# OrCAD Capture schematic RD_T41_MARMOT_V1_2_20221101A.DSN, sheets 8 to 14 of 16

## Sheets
8 PAGE08_AUDIO: size A3
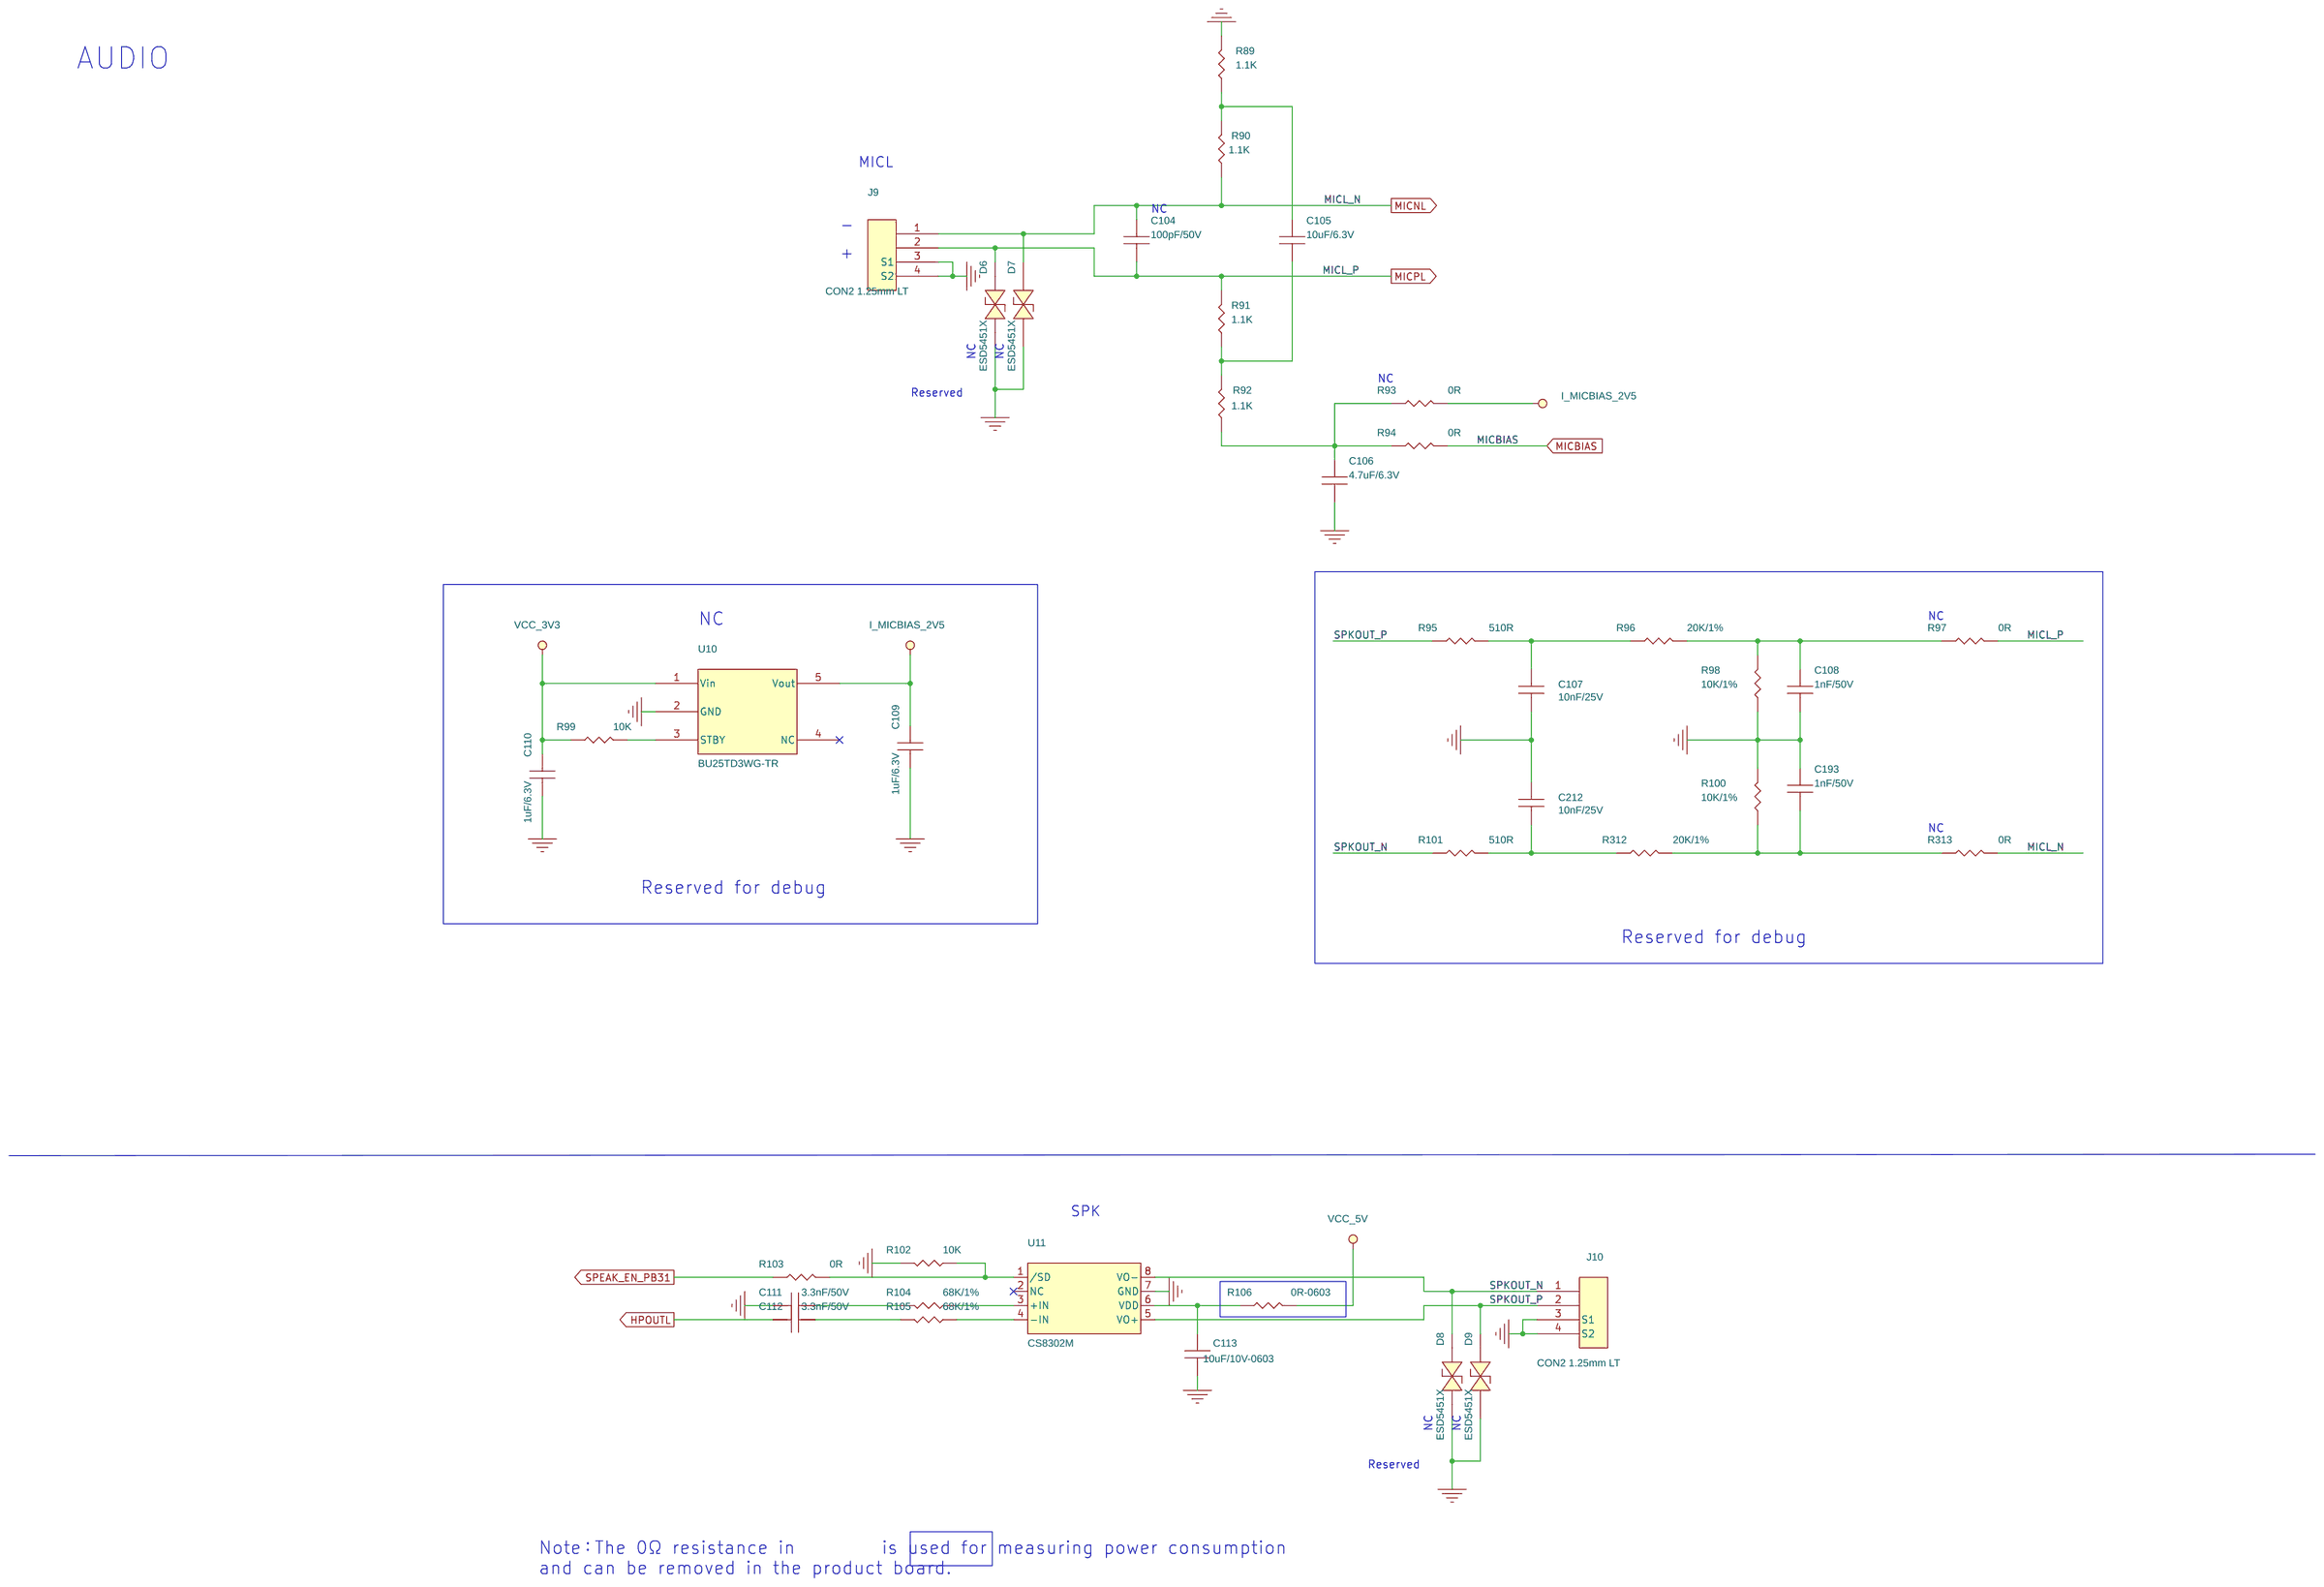
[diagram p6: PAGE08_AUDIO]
9 PAGE09_CAMERA: size A3
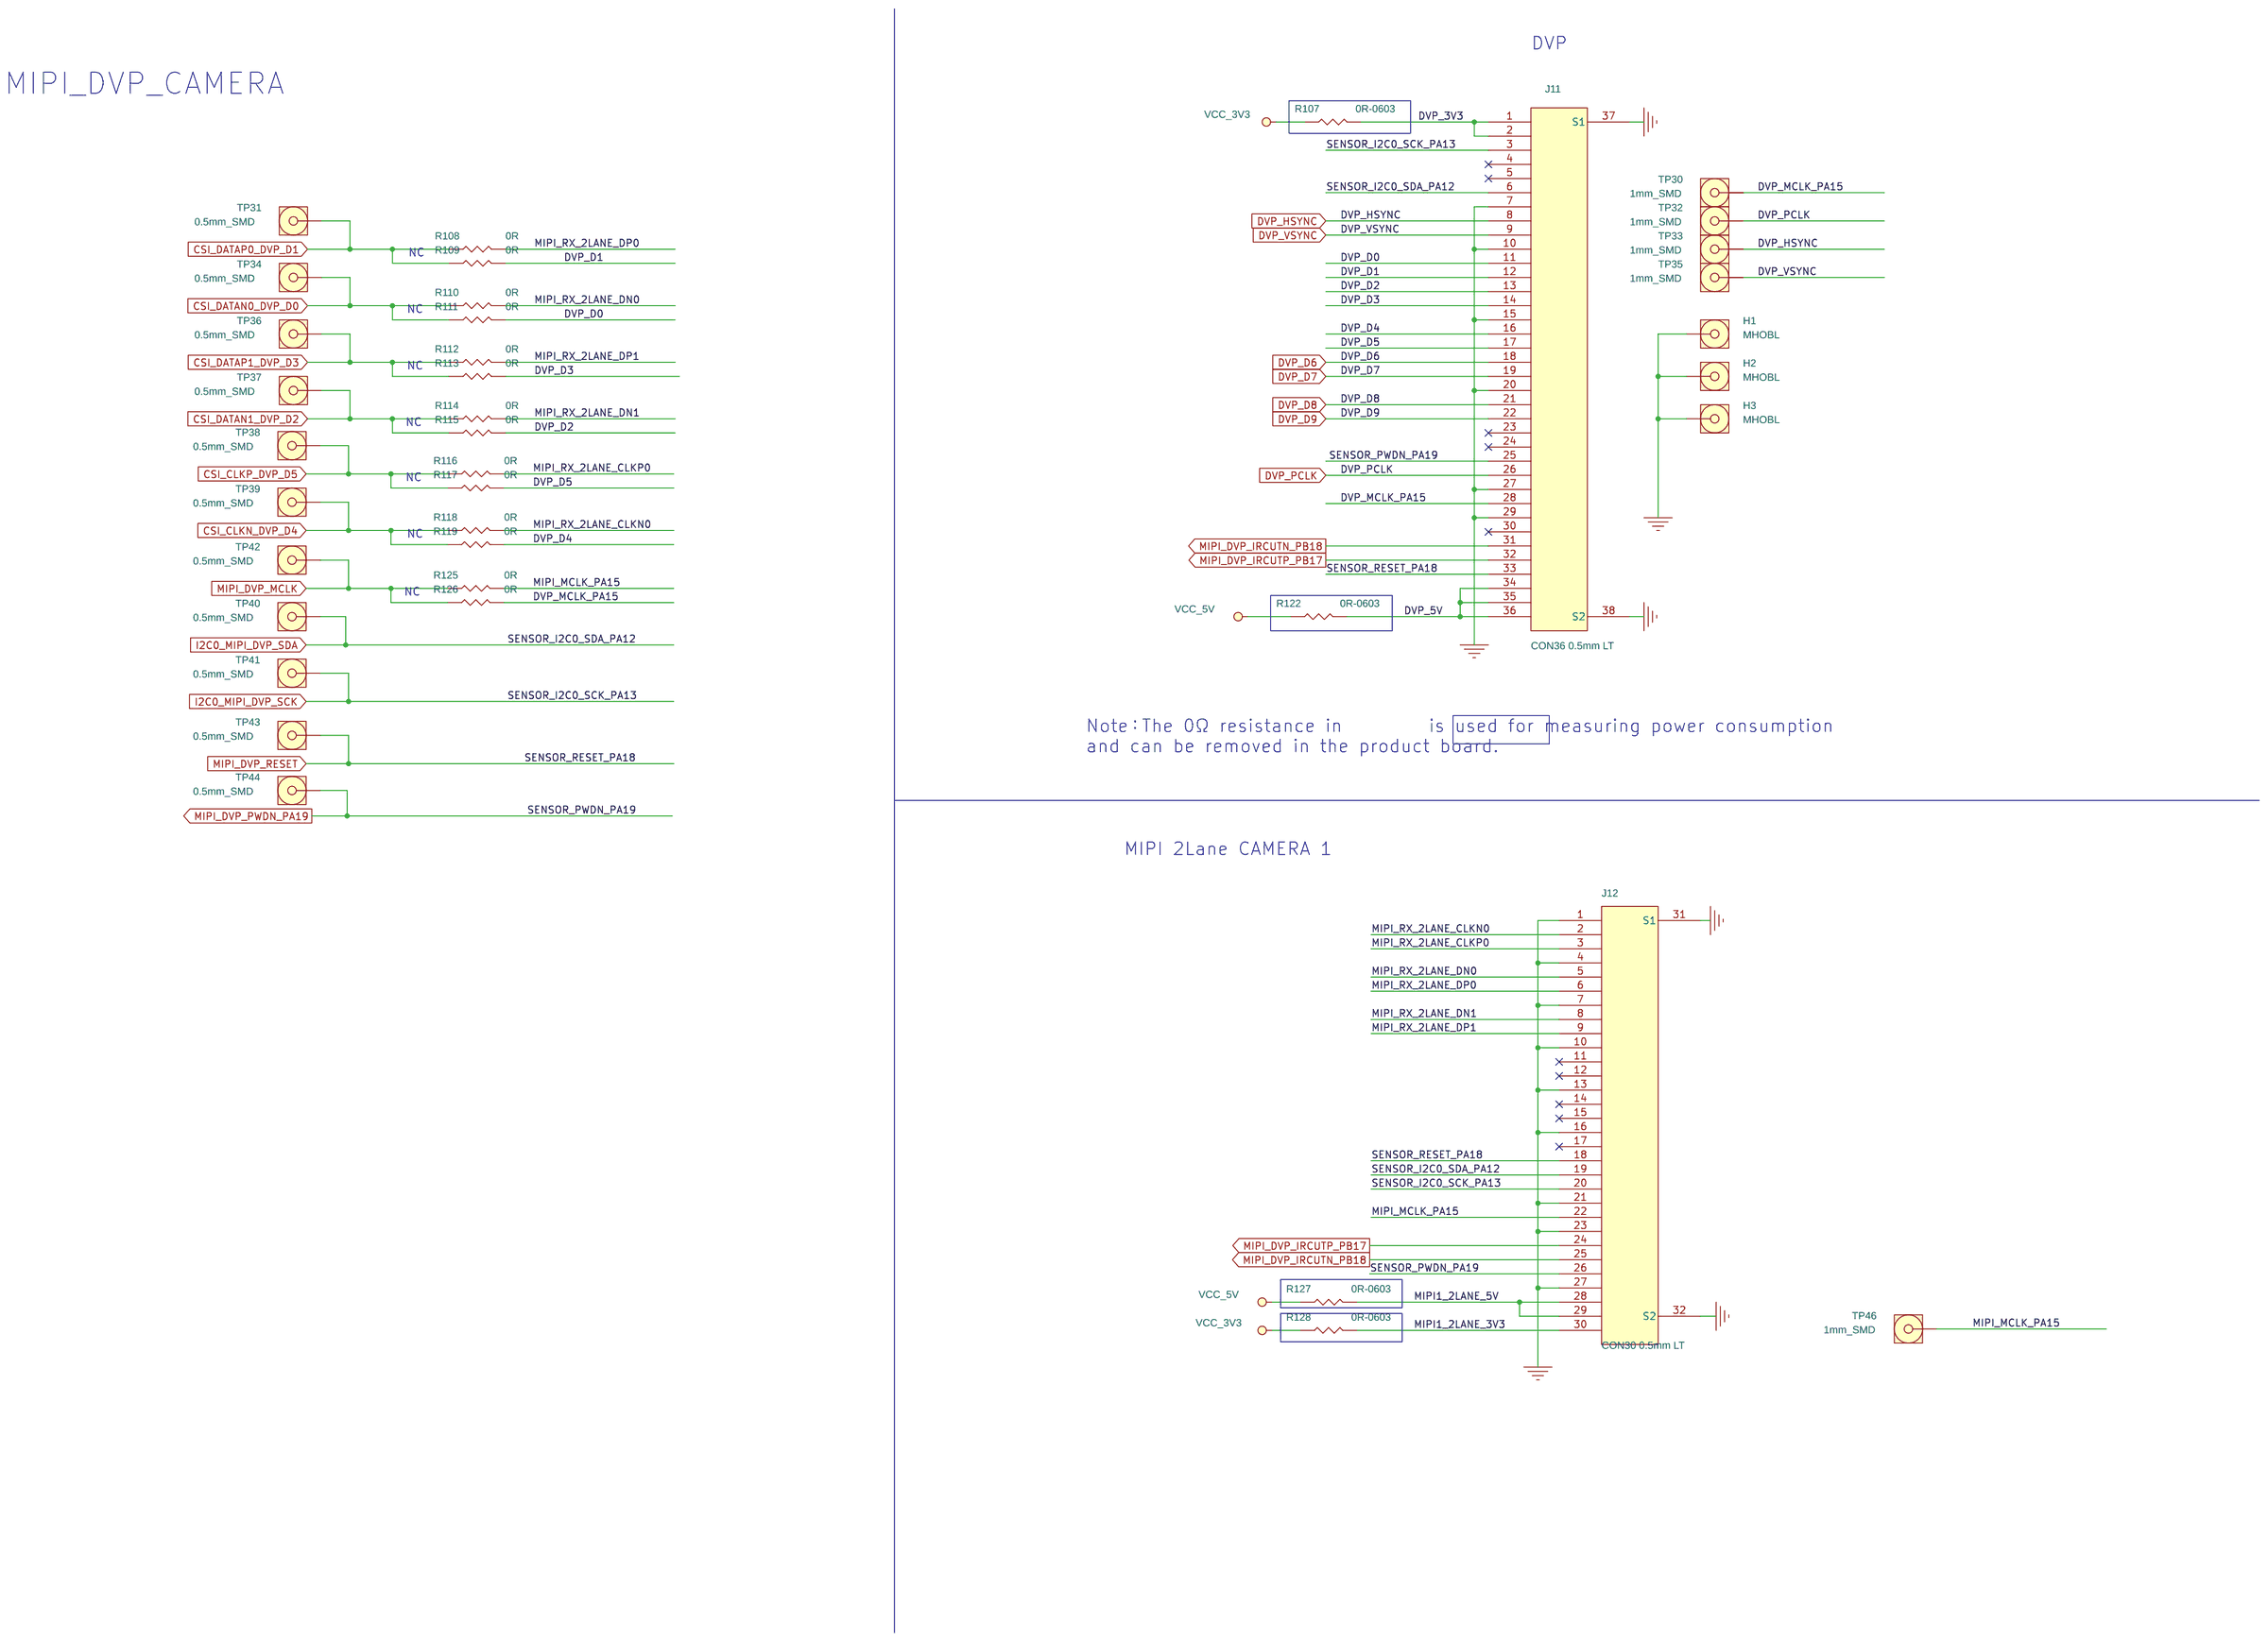
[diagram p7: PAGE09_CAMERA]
10 PAGE10_EMMC_DMIC: size A3
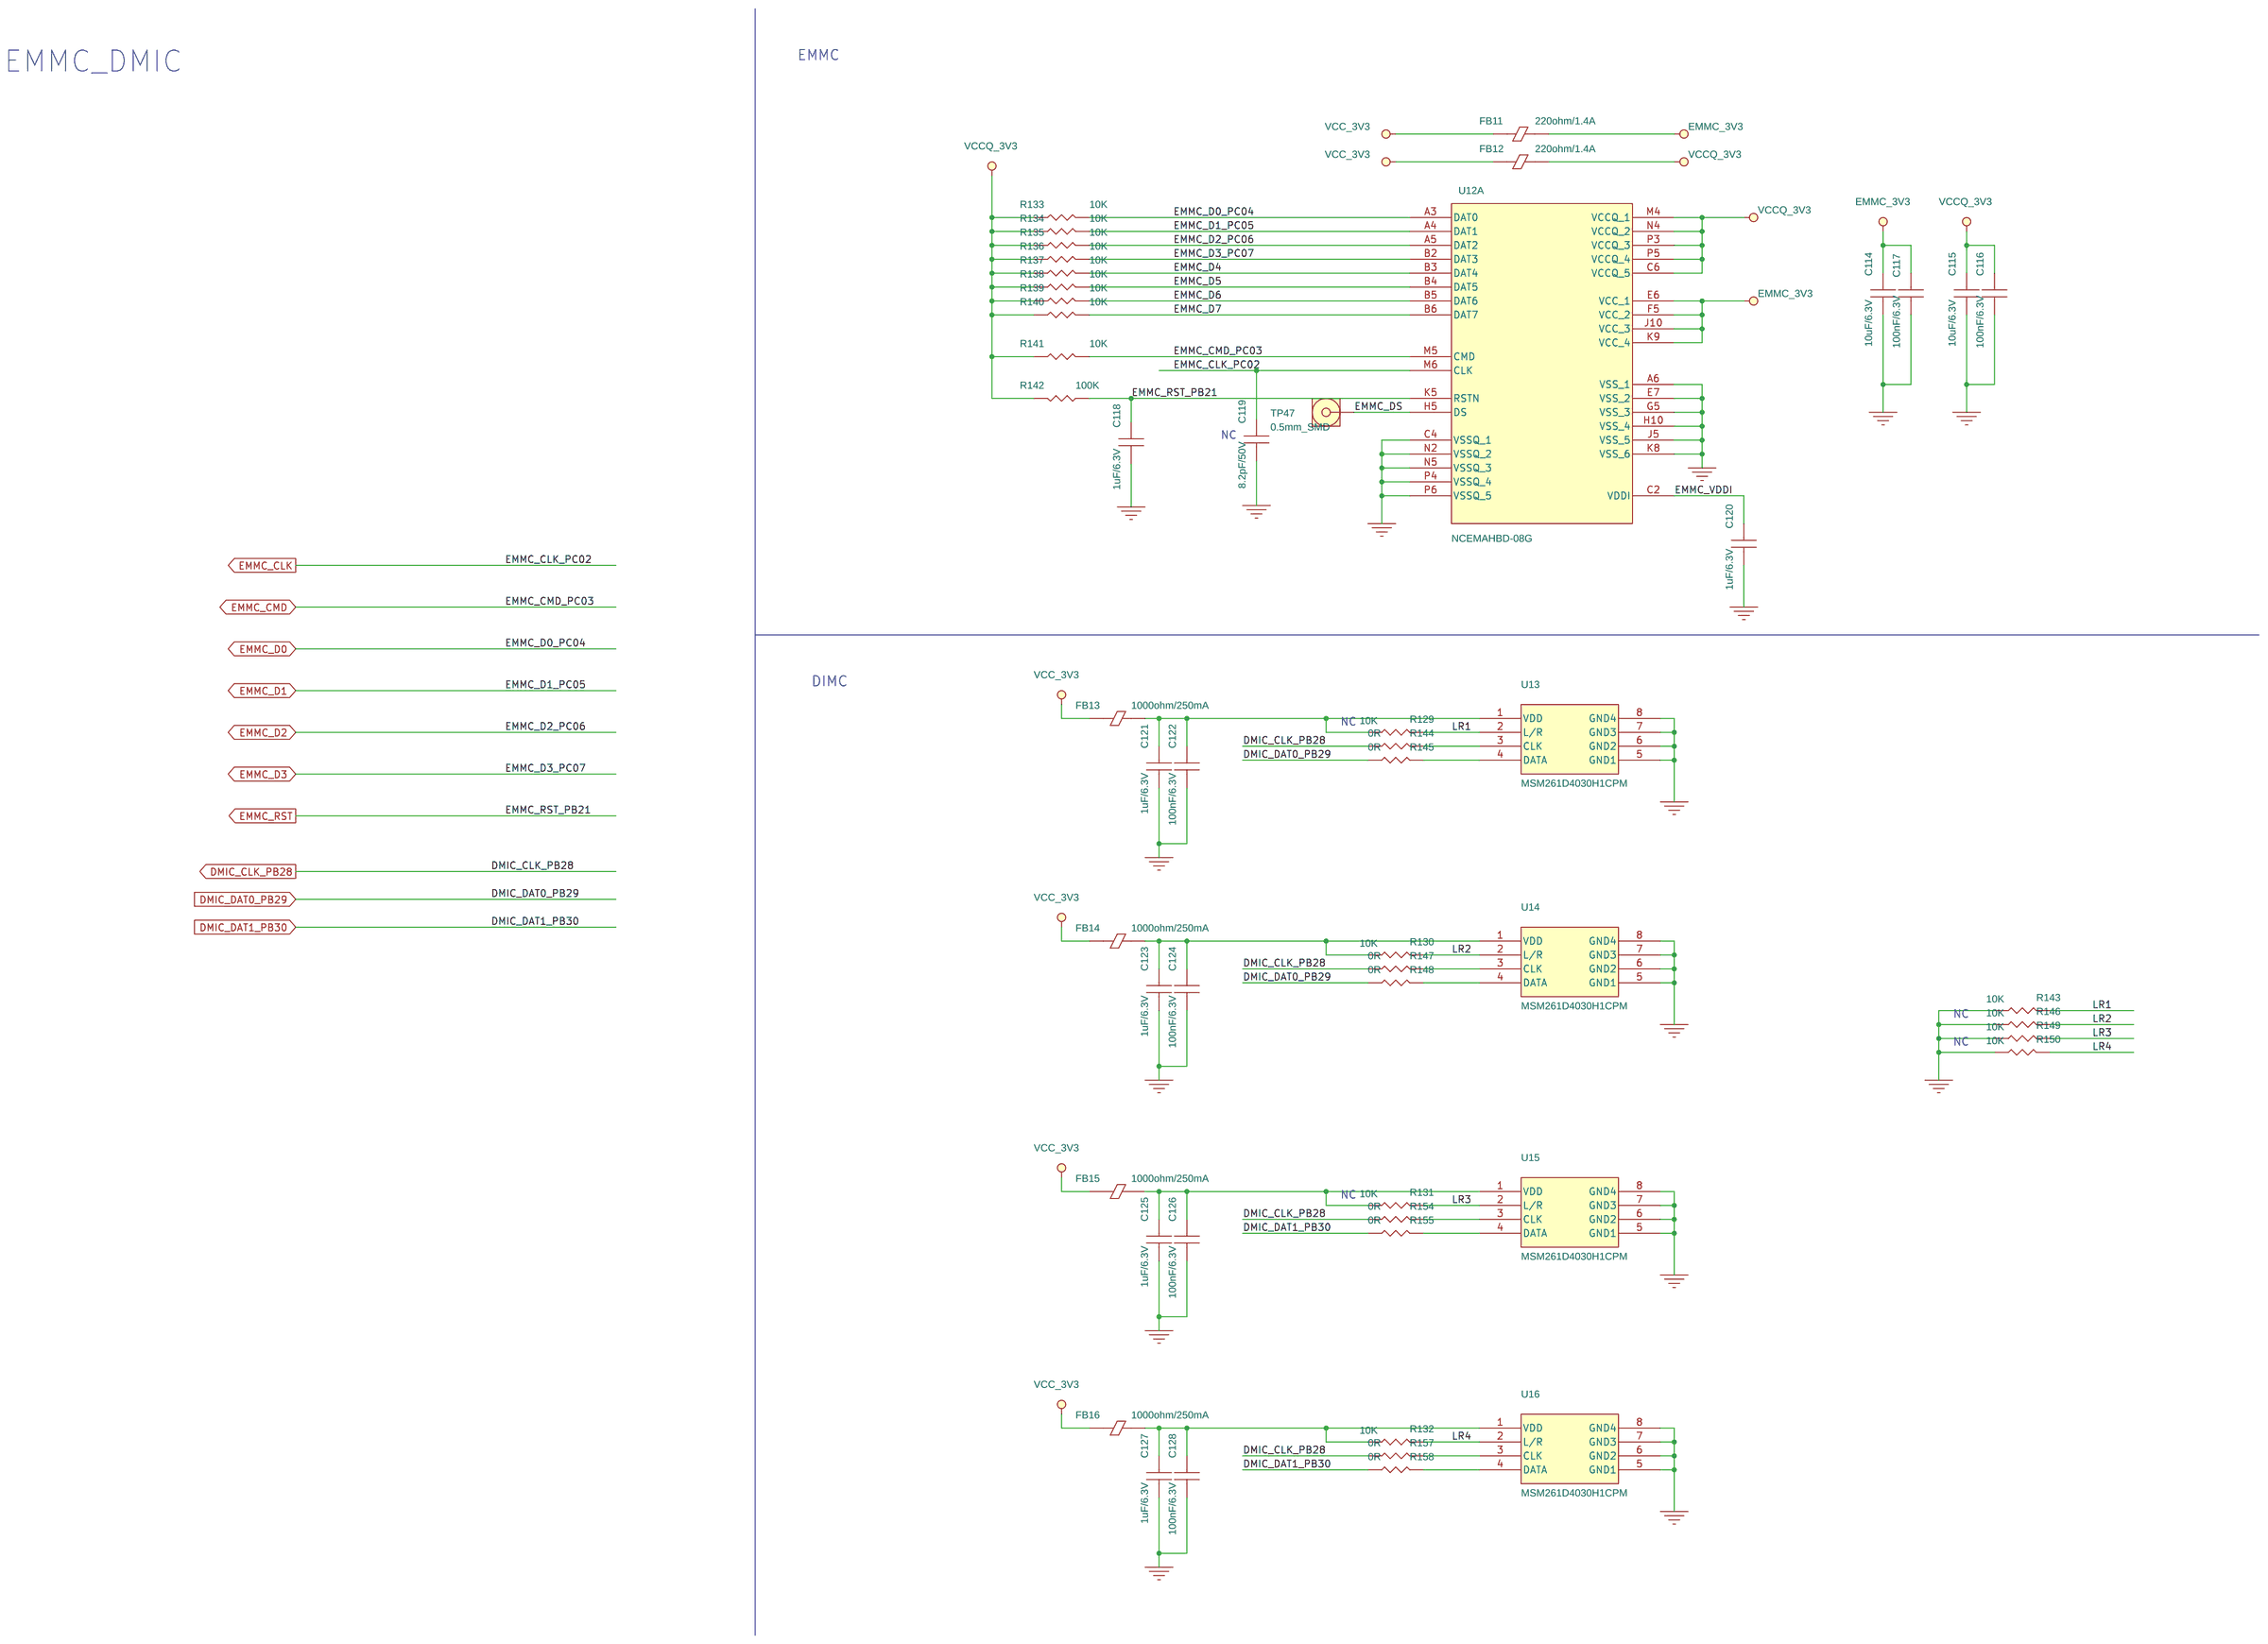
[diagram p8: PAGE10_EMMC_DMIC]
11 PAGE11_I2S_CODEC: size A3
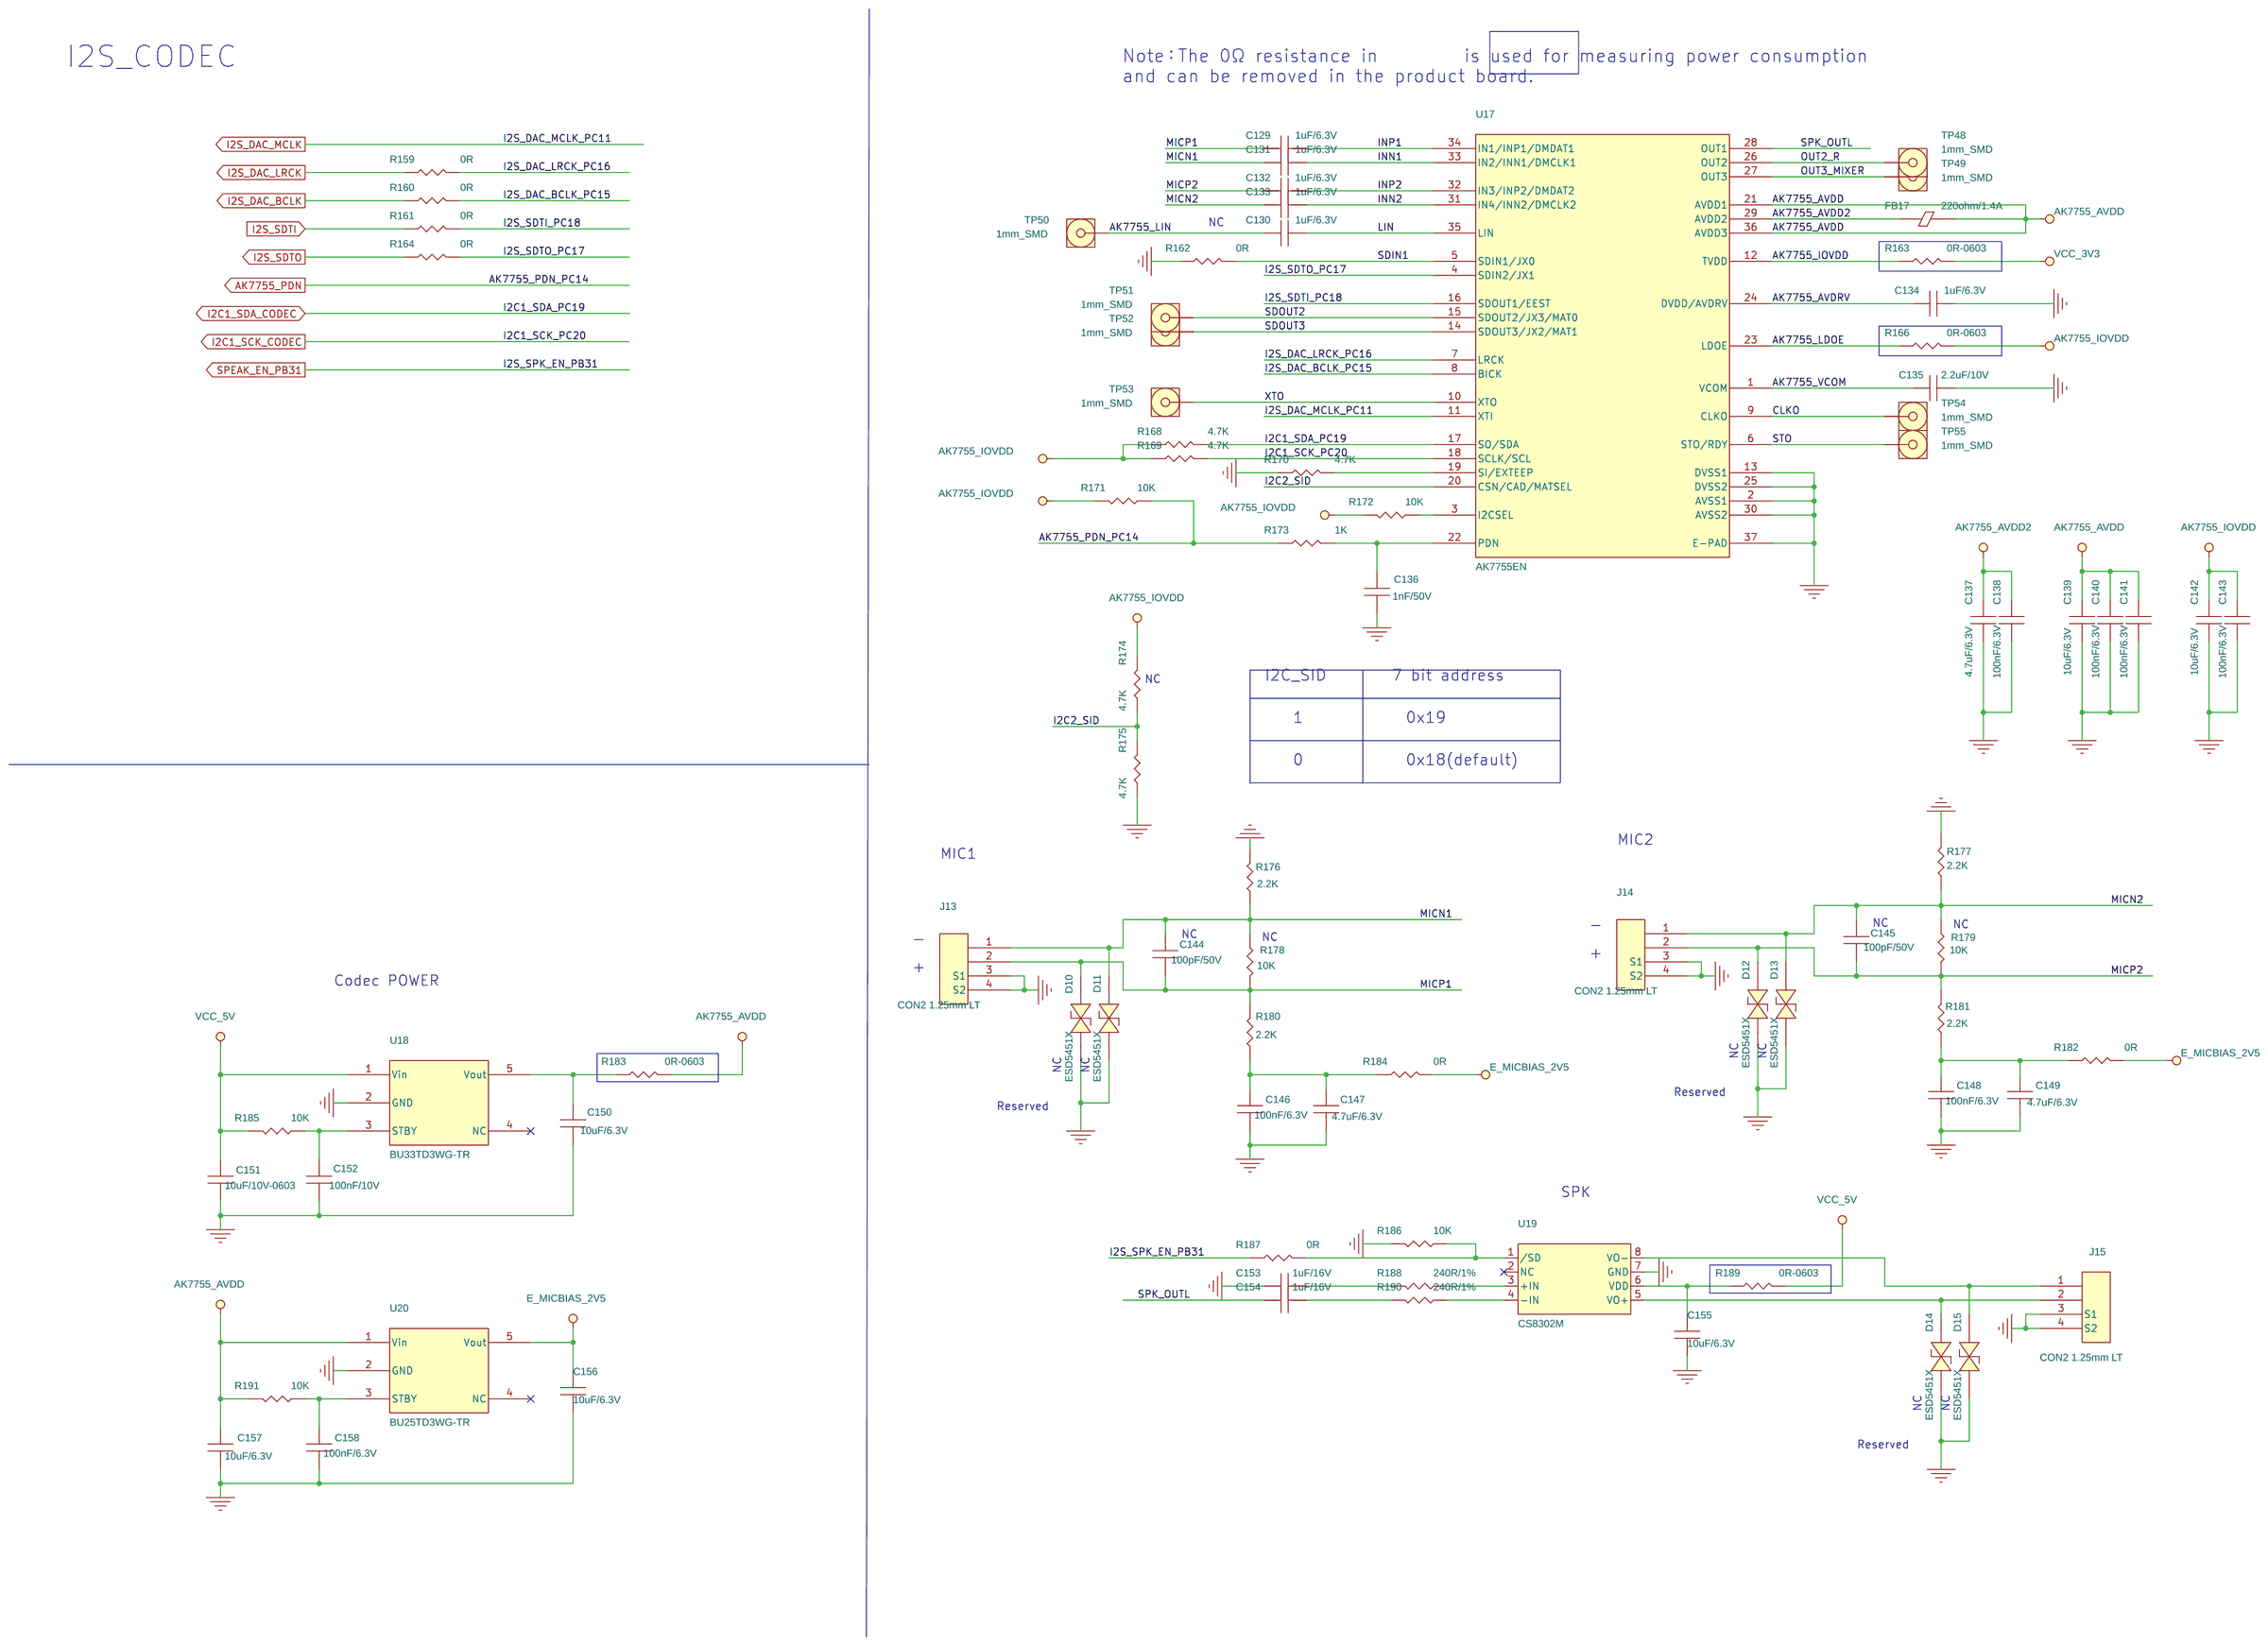
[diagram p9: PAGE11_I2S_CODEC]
12 PAGE12_SD_WIFI_AF_MOTOR: size A3
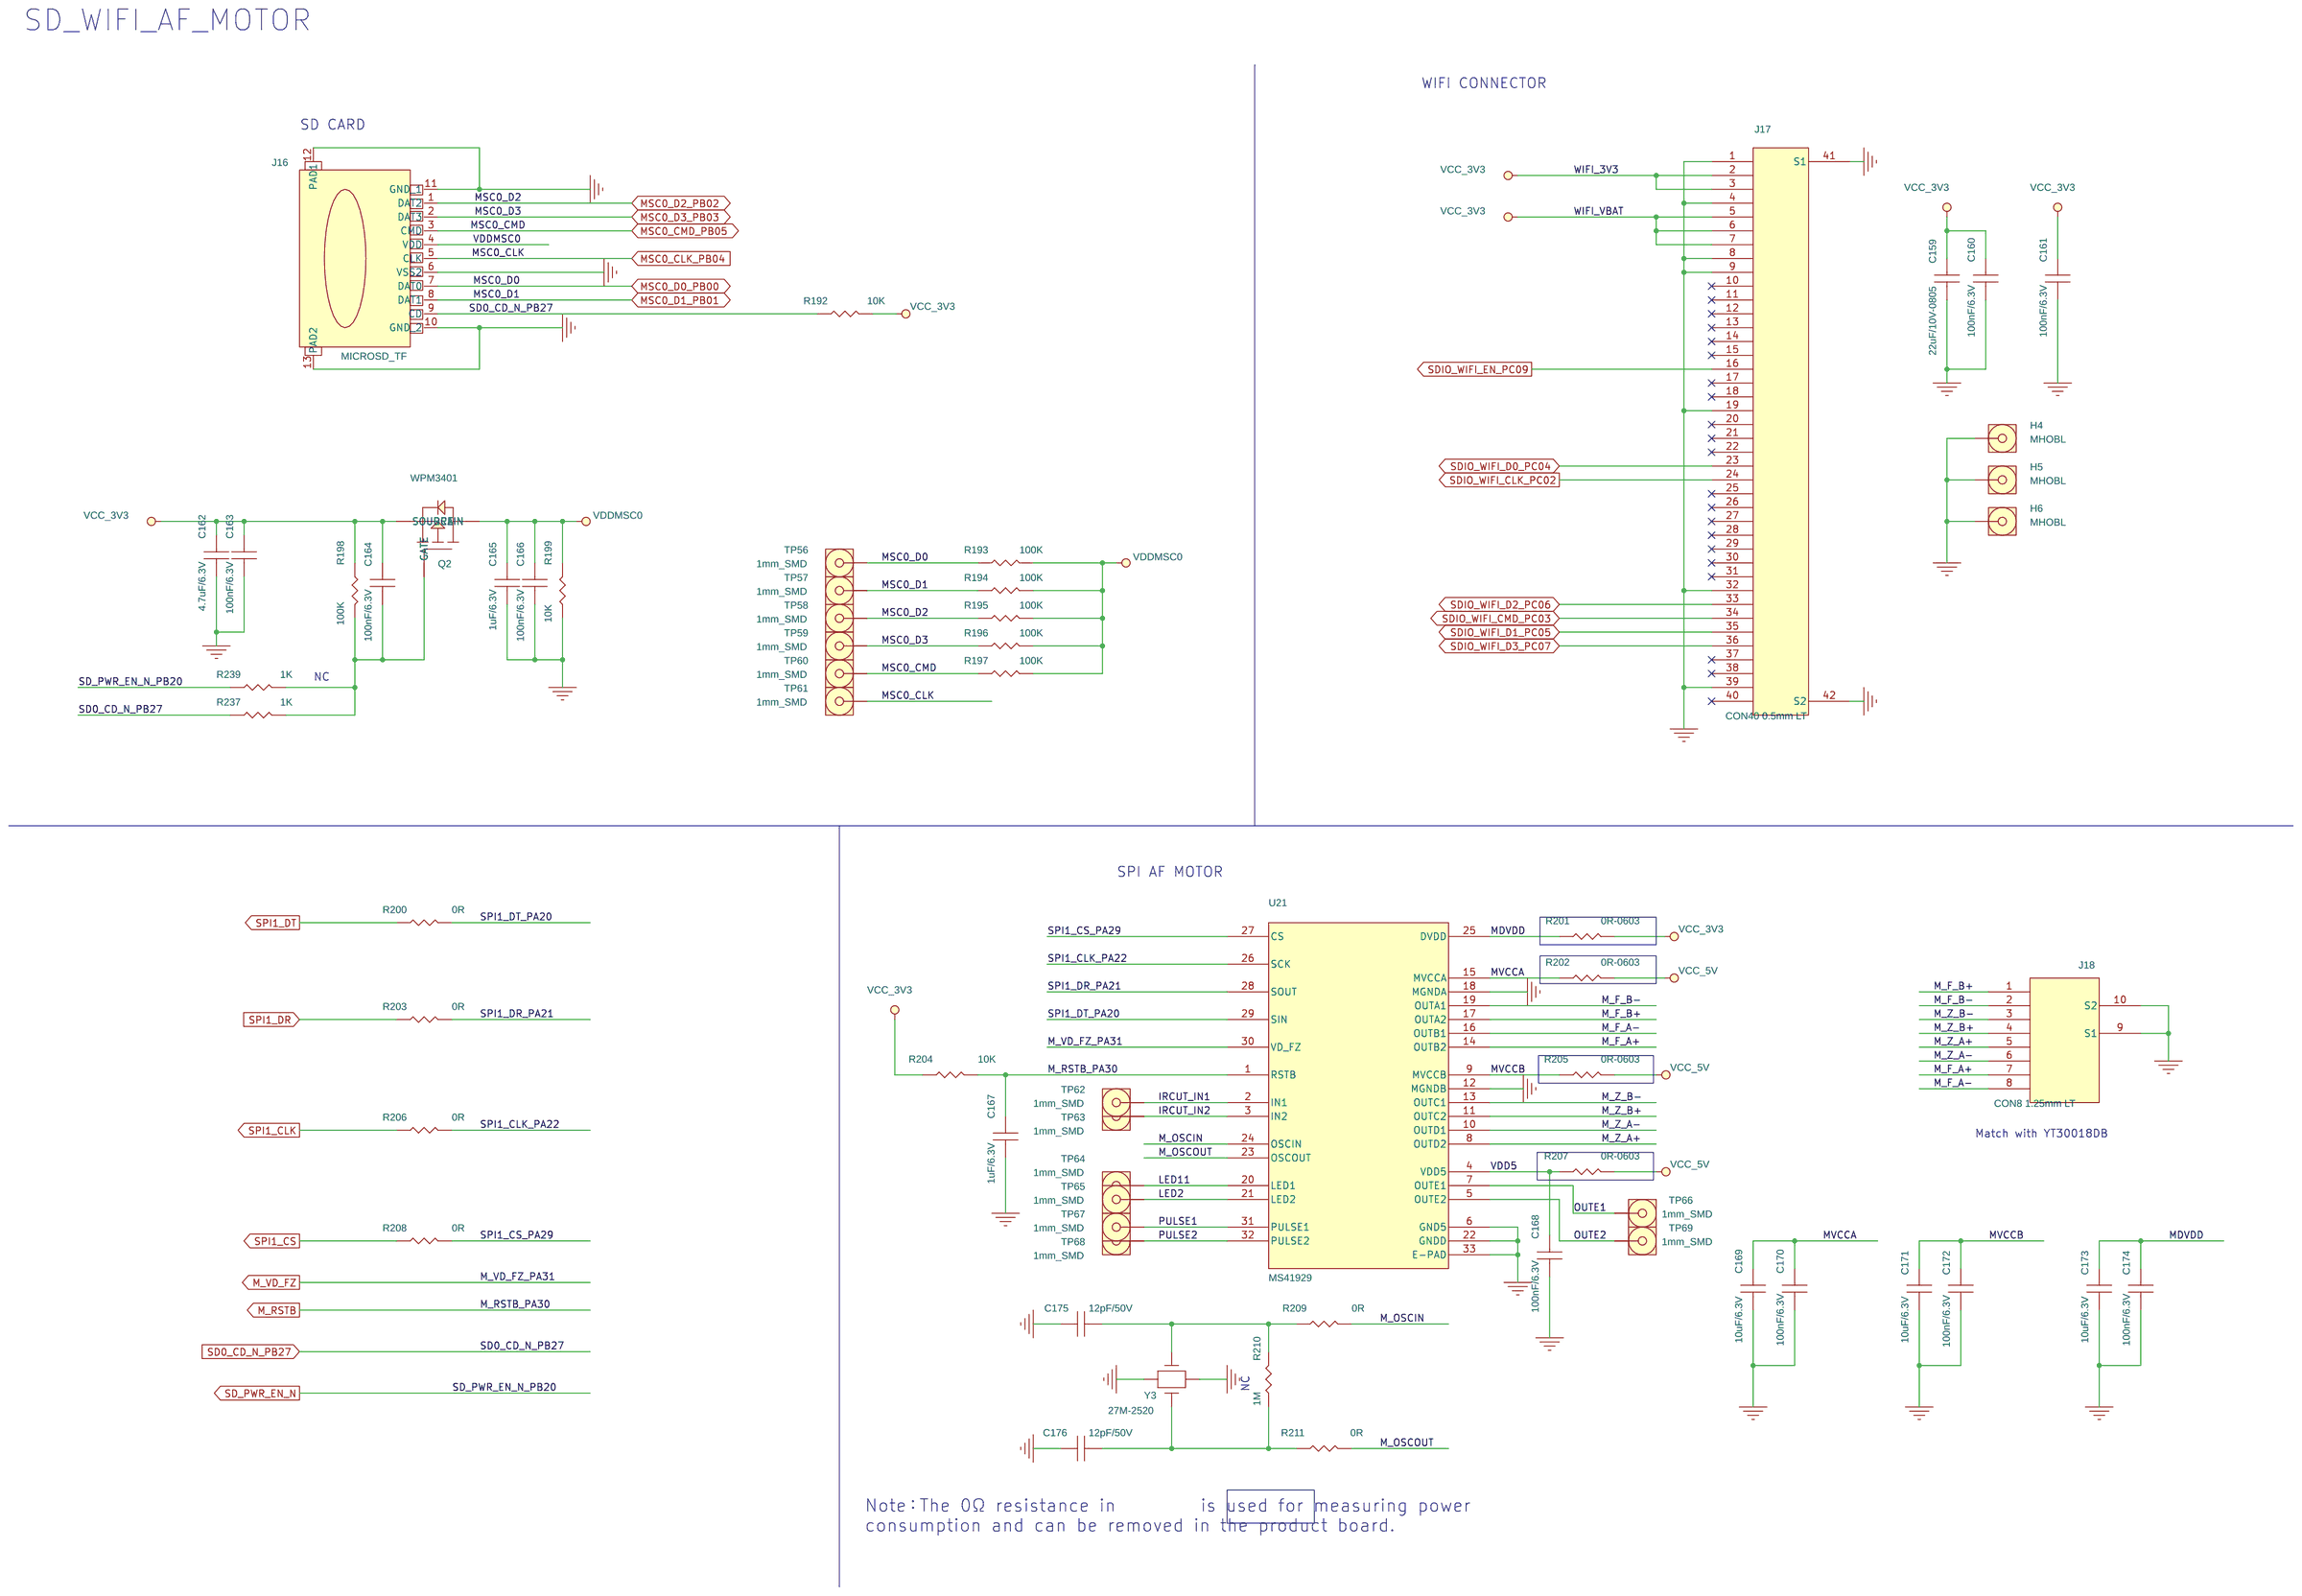
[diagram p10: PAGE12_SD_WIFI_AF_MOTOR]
13 PAGE13_ETH_PHY: size A3
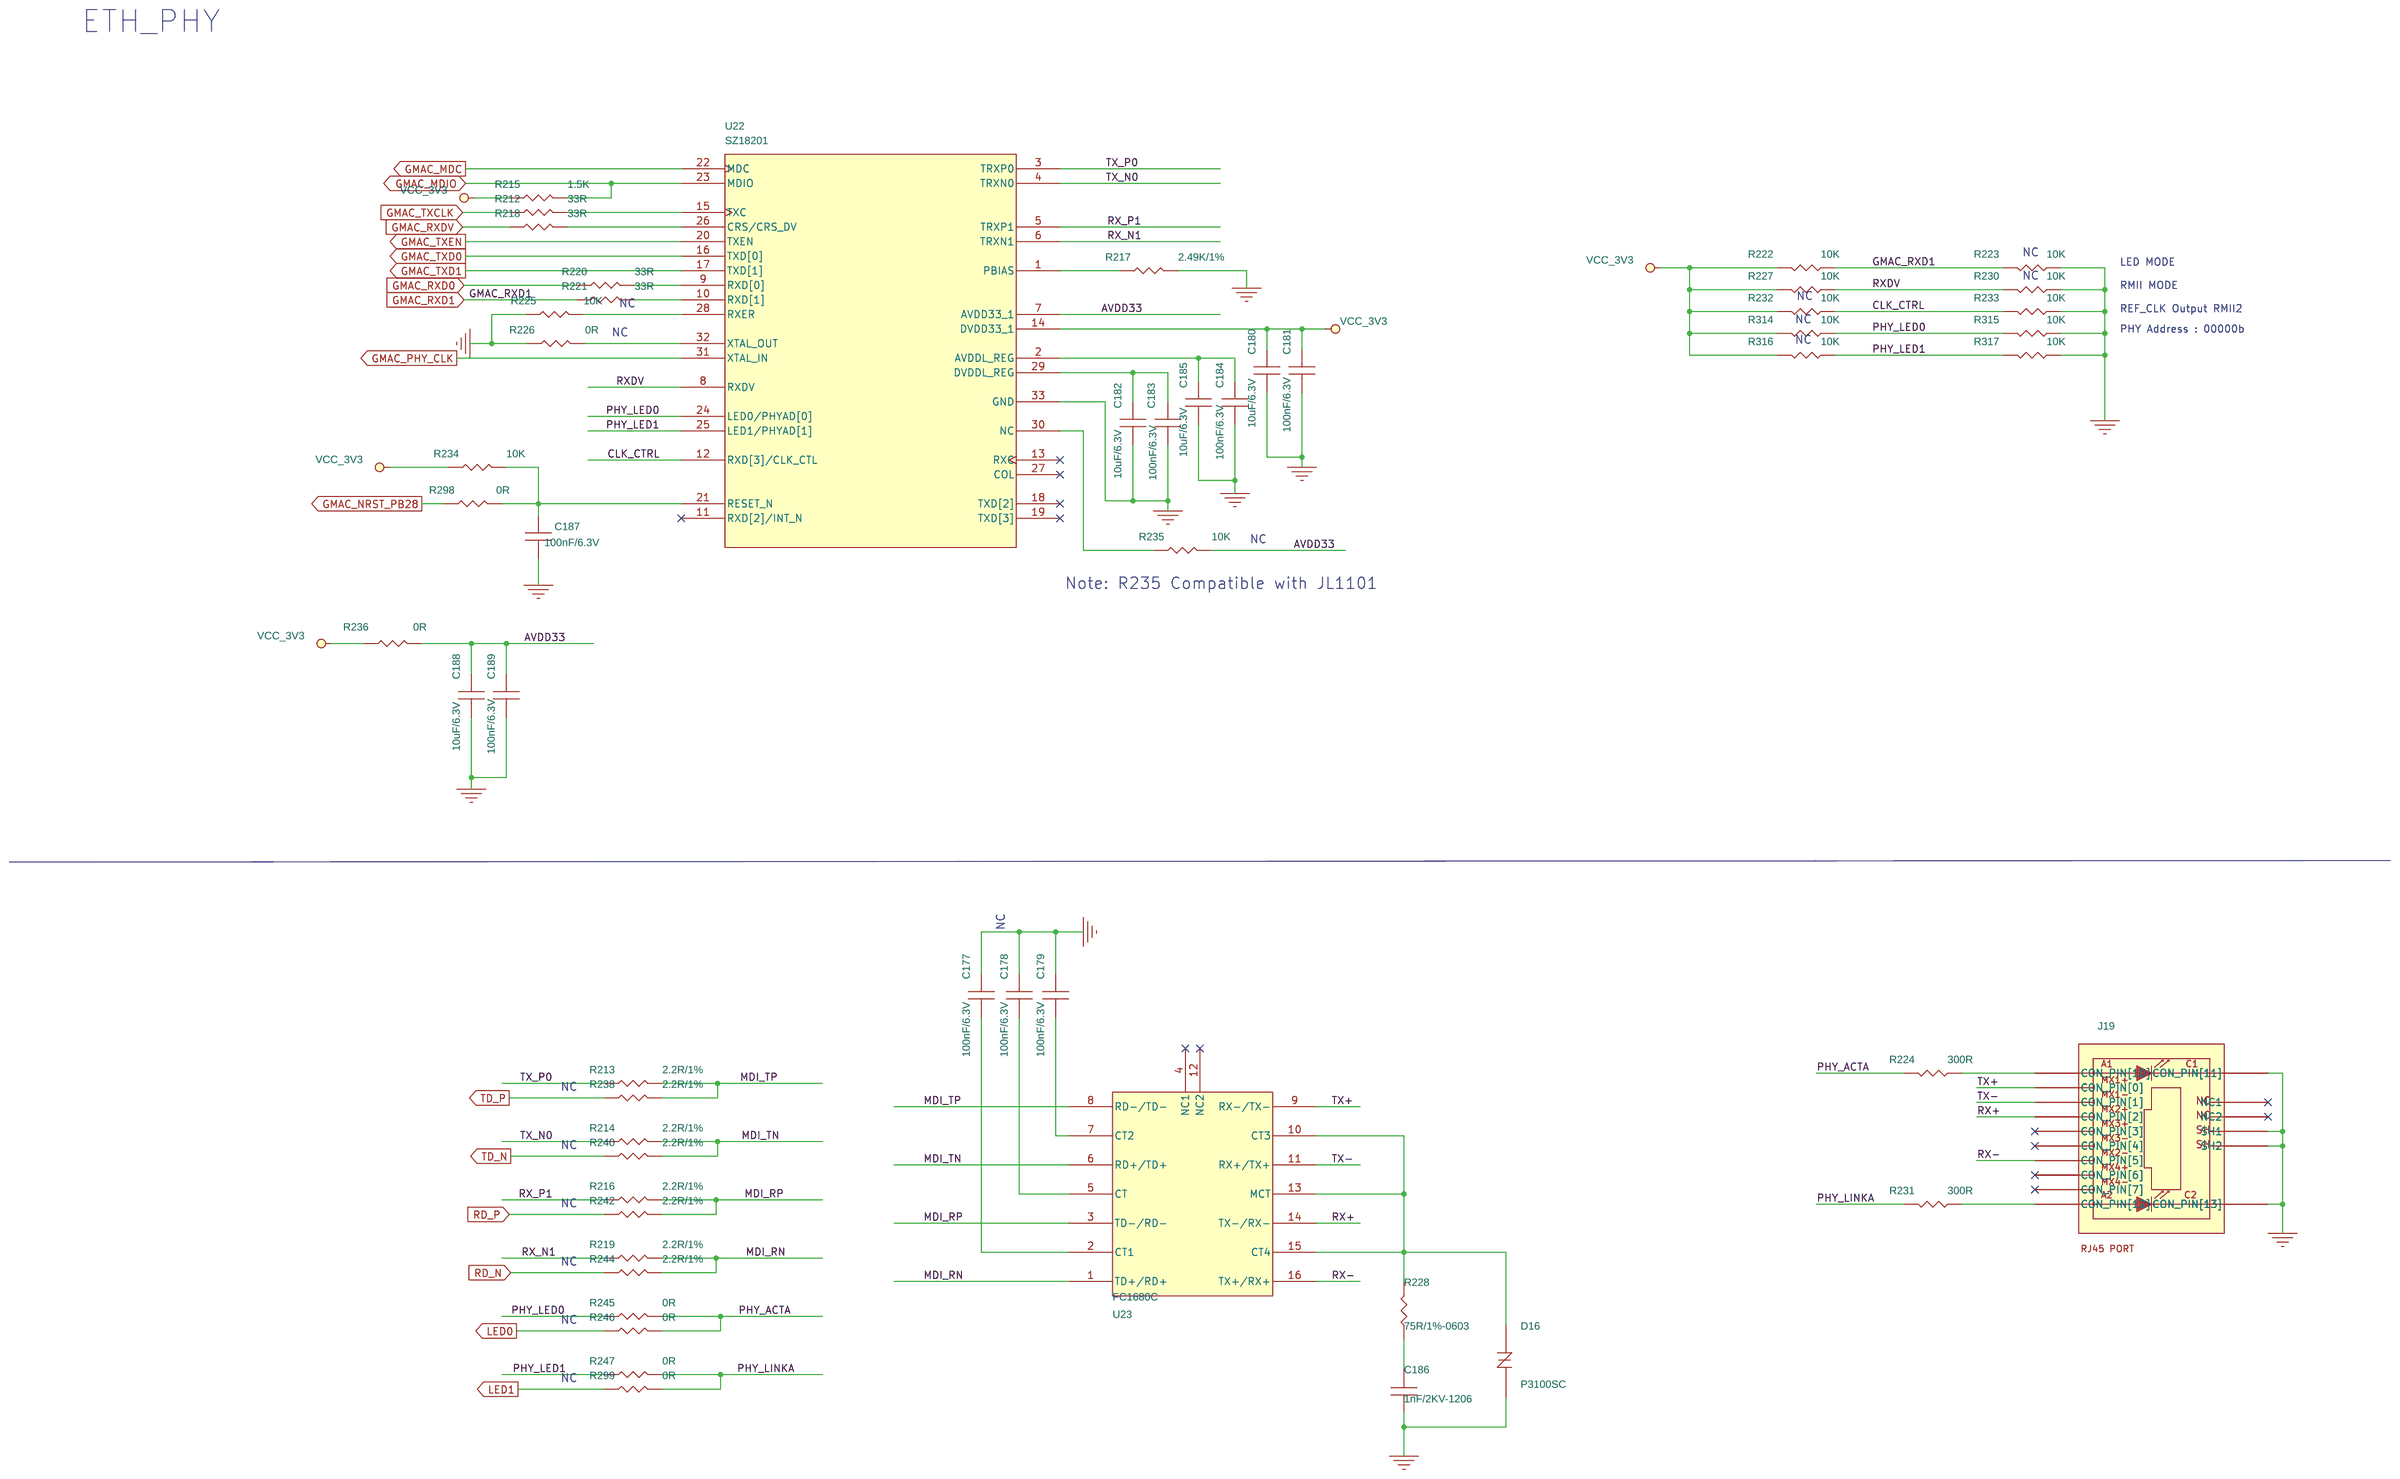
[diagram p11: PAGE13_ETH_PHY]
14 PAGE14_RGB_MIPI_LCD: size A3
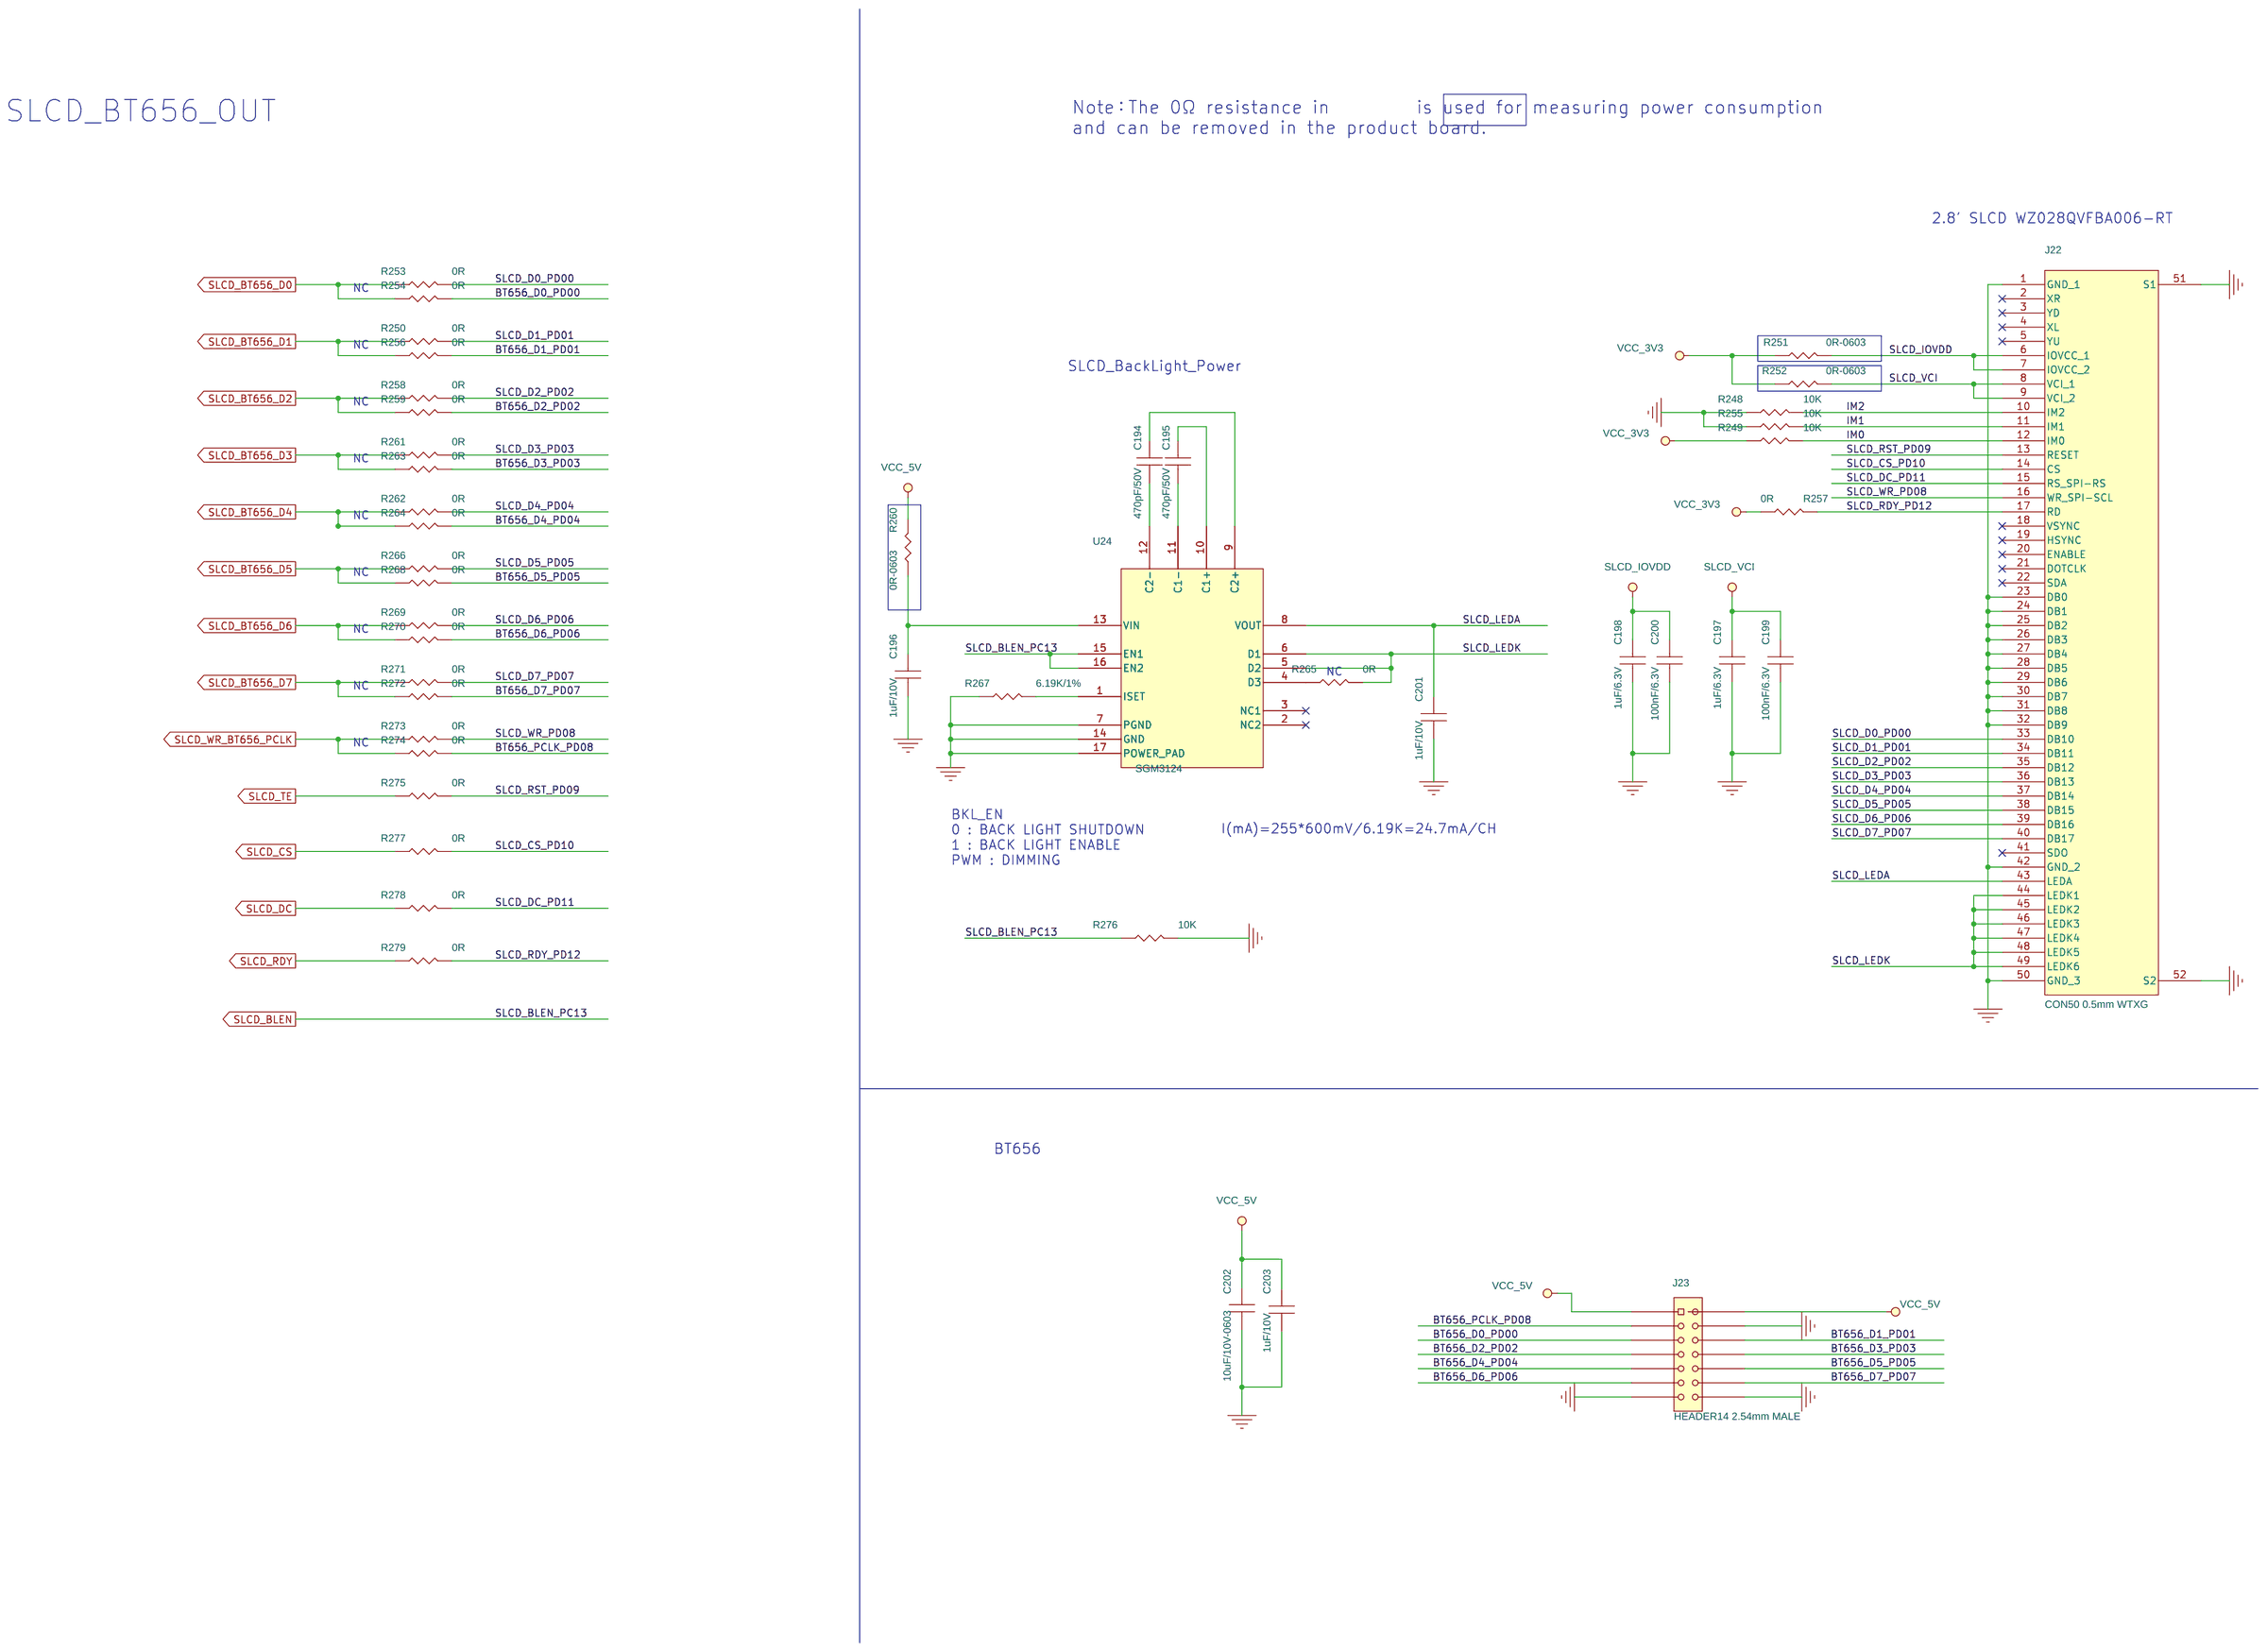
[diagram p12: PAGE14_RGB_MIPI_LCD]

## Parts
sheet PAGE08_AUDIO
C104  100pF/50V  [C0402]
C105  10uF/6.3V  [C0402_E]
C106  4.7uF/6.3V  [C0402]
C107  10nF/25V  [C0402]
C108  1nF/50V  [C0402]
C109  1uF/6.3V  [C0402]
C110  1uF/6.3V  [C0402]
C111  3.3nF/50V  [C0402]
C112  3.3nF/50V  [C0402]
C113  10uF/10V-0603  [C0603]
C193  1nF/50V  [C0402]
C212  10nF/25V  [C0402]
D6  ESD5451X  [ESD0402]
D7  ESD5451X  [ESD0402]
D8  ESD5451X  [ESD0402]
D9  ESD5451X  [ESD0402]
J9  CON2 1.25mm LT  [CON2-1D25-LT]
J10  CON2 1.25mm LT  [CON2-1D25-LT]
R89  1.1K  [R0402]
R90  1.1K  [R0402]
R91  1.1K  [R0402]
R92  1.1K  [R0402]
R93  0R  [R0402]
R94  0R  [R0402]
R95  510R  [R0402]
R96  20K/1%  [R0402]
R97  0R  [R0402]
R98  10K/1%  [R0402]
R99  10K  [R0402]
R100  10K/1%  [R0402]
R101  510R  [R0402]
R102  10K  [R0402]
R103  0R  [R0402]
R104  68K/1%  [R0402]
R105  68K/1%  [R0402]
R106  0R-0603  [R0603]
R312  20K/1%  [R0402]
R313  0R  [R0402]
U10  BU25TD3WG-TR  [SOT23-5]
U11  CS8302M  [MSOP8_0D65]
sheet PAGE09_CAMERA
H1  MHOBL  [MHOLE_3D0X2D0]
H2  MHOBL  [MHOLE_3D0X2D0]
H3  MHOBL  [MHOLE_3D0X2D0]
J11  CON36 0.5mm LT  [FPC-CON36-0D5-LT]
J12  CON30 0.5mm LT  [FPC-CON30-0D5-LT]
R107  0R-0603  [R0603]
R108  0R  [R0402]
R109  0R  [R0402]
R110  0R  [R0402]
R111  0R  [R0402]
R112  0R  [R0402]
R113  0R  [R0402]
R114  0R  [R0402]
R115  0R  [R0402]
R116  0R  [R0402]
R117  0R  [R0402]
R118  0R  [R0402]
R119  0R  [R0402]
R122  0R-0603  [R0603]
R125  0R  [R0402]
R126  0R  [R0402]
R127  0R-0603  [R0603]
R128  0R-0603  [R0603]
TP30  1mm_SMD  [TEST_SMD]
TP31  0.5mm_SMD  [TEST_SMD_0D5]
TP32  1mm_SMD  [TEST_SMD]
TP33  1mm_SMD  [TEST_SMD]
TP34  0.5mm_SMD  [TEST_SMD_0D5]
TP35  1mm_SMD  [TEST_SMD]
TP36  0.5mm_SMD  [TEST_SMD_0D5]
TP37  0.5mm_SMD  [TEST_SMD_0D5]
TP38  0.5mm_SMD  [TEST_SMD_0D5]
TP39  0.5mm_SMD  [TEST_SMD_0D5]
TP40  0.5mm_SMD  [TEST_SMD_0D5]
TP41  0.5mm_SMD  [TEST_SMD_0D5]
TP42  0.5mm_SMD  [TEST_SMD_0D5]
TP43  0.5mm_SMD  [TEST_SMD_0D5]
TP44  0.5mm_SMD  [TEST_SMD_0D5]
TP46  1mm_SMD  [TEST_SMD]
sheet PAGE10_EMMC_DMIC
C114  10uF/6.3V  [C0402_E]
C115  10uF/6.3V  [C0402_E]
C116  100nF/6.3V  [C0402]
C117  100nF/6.3V  [C0402]
C118  1uF/6.3V  [C0402]
C119  8.2pF/50V  [C0402]
C120  1uF/6.3V  [C0402]
C121  1uF/6.3V  [C0402]
C122  100nF/6.3V  [C0402]
C123  1uF/6.3V  [C0402]
C124  100nF/6.3V  [C0402]
C125  1uF/6.3V  [C0402]
C126  100nF/6.3V  [C0402]
C127  1uF/6.3V  [C0402]
C128  100nF/6.3V  [C0402]
FB11  220ohm/1.4A  [FB0402]
FB12  220ohm/1.4A  [FB0402]
FB13  1000ohm/250mA  [FB0402]
FB14  1000ohm/250mA  [FB0402]
FB15  1000ohm/250mA  [FB0402]
FB16  1000ohm/250mA  [FB0402]
R129  10K  [R0402]
R130  10K  [R0402]
R131  10K  [R0402]
R132  10K  [R0402]
R133  10K  [R0402]
R134  10K  [R0402]
R135  10K  [R0402]
R136  10K  [R0402]
R137  10K  [R0402]
R138  10K  [R0402]
R139  10K  [R0402]
R140  10K  [R0402]
R141  10K  [R0402]
R142  100K  [R0402]
R143  10K  [R0402]
R144  0R  [R0402]
R145  0R  [R0402]
R146  10K  [R0402]
R147  0R  [R0402]
R148  0R  [R0402]
R149  10K  [R0402]
R150  10K  [R0402]
R154  0R  [R0402]
R155  0R  [R0402]
R157  0R  [R0402]
R158  0R  [R0402]
TP47  0.5mm_SMD  [TEST_SMD_0D5]
U12  NCEMAHBD-08G  [BGA153_0D5_NCEMAHBD-08G]  (section A)
U13  MSM261D4030H1CPM  [HCLGA3X4_MSM261D4030H1]
U14  MSM261D4030H1CPM  [HCLGA3X4_MSM261D4030H1]
U15  MSM261D4030H1CPM  [HCLGA3X4_MSM261D4030H1]
U16  MSM261D4030H1CPM  [HCLGA3X4_MSM261D4030H1]
sheet PAGE11_I2S_CODEC
C129  1uF/6.3V  [C0402]
C130  1uF/6.3V  [C0402]
C131  1uF/6.3V  [C0402]
C132  1uF/6.3V  [C0402]
C133  1uF/6.3V  [C0402]
C134  1uF/6.3V  [C0402]
C135  2.2uF/10V  [C0402]
C136  1nF/50V  [C0402]
C137  4.7uF/6.3V  [C0402]
C138  100nF/6.3V  [C0402]
C139  10uF/6.3V  [C0402_E]
C140  100nF/6.3V  [C0402]
C141  100nF/6.3V  [C0402]
C142  10uF/6.3V  [C0402_E]
C143  100nF/6.3V  [C0402]
C144  100pF/50V  [C0402]
C145  100pF/50V  [C0402]
C146  100nF/6.3V  [C0402]
C147  4.7uF/6.3V  [C0402]
C148  100nF/6.3V  [C0402]
C149  4.7uF/6.3V  [C0402]
C150  10uF/6.3V  [C0402_E]
C151  10uF/10V-0603  [C0603]
C152  100nF/10V  [C0402]
C153  1uF/16V  [C0402]
C154  1uF/16V  [C0402]
C155  10uF/6.3V  [C0402_E]
C156  10uF/6.3V  [C0402_E]
C157  10uF/6.3V  [C0402_E]
C158  100nF/6.3V  [C0402]
D10  ESD5451X  [ESD0402]
D11  ESD5451X  [ESD0402]
D12  ESD5451X  [ESD0402]
D13  ESD5451X  [ESD0402]
D14  ESD5451X  [ESD0402]
D15  ESD5451X  [ESD0402]
FB17  220ohm/1.4A  [FB0402]
J13  CON2 1.25mm LT  [CON2-1D25-LT]
J14  CON2 1.25mm LT  [CON2-1D25-LT]
J15  CON2 1.25mm LT  [CON2-1D25-LT]
R159  0R  [R0402]
R160  0R  [R0402]
R161  0R  [R0402]
R162  0R  [R0402]
R163  0R-0603  [R0603]
R164  0R  [R0402]
R166  0R-0603  [R0603]
R168  4.7K  [R0402]
R169  4.7K  [R0402]
R170  4.7K  [R0402]
R171  10K  [R0402]
R172  10K  [R0402]
R173  1K  [R0402]
R174  4.7K  [R0402]
R175  4.7K  [R0402]
R176  2.2K  [R0402]
R177  2.2K  [R0402]
R178  10K  [R0402]
R179  10K  [R0402]
R180  2.2K  [R0402]
R181  2.2K  [R0402]
R182  0R  [R0402]
R183  0R-0603  [R0603]
R184  0R  [R0402]
R185  10K  [R0402]
R186  10K  [R0402]
R187  0R  [R0402]
R188  240R/1%  [R0402]
R189  0R-0603  [R0603]
R190  240R/1%  [R0402]
R191  10K  [R0402]
TP48  1mm_SMD  [TEST_SMD]
TP49  1mm_SMD  [TEST_SMD]
TP50  1mm_SMD  [TEST_SMD]
TP51  1mm_SMD  [TEST_SMD]
TP52  1mm_SMD  [TEST_SMD]
TP53  1mm_SMD  [TEST_SMD]
TP54  1mm_SMD  [TEST_SMD]
TP55  1mm_SMD  [TEST_SMD]
U17  AK7755EN  [QFN36_0D5_AK7755]
U18  BU33TD3WG-TR  [SOT23-5]
U19  CS8302M  [MSOP8_0D65]
U20  BU25TD3WG-TR  [SOT23-5]
sheet PAGE12_SD_WIFI_AF_MOTOR
C159  22uF/10V-0805  [C0805]
C160  100nF/6.3V  [C0402]
C161  100nF/6.3V  [C0402]
C162  4.7uF/6.3V  [C0402]
C163  100nF/6.3V  [C0402]
C164  100nF/6.3V  [C0402]
C165  1uF/6.3V  [C0402]
C166  100nF/6.3V  [C0402]
C167  1uF/6.3V  [C0402]
C168  100nF/6.3V  [C0402]
C169  10uF/6.3V  [C0402_E]
C170  100nF/6.3V  [C0402]
C171  10uF/6.3V  [C0402_E]
C172  100nF/6.3V  [C0402]
C173  10uF/6.3V  [C0402_E]
C174  100nF/6.3V  [C0402]
C175  12pF/50V  [C0402]
C176  12pF/50V  [C0402]
H4  MHOBL  [MHOLE_3D0X2D0]
H5  MHOBL  [MHOLE_3D0X2D0]
H6  MHOBL  [MHOLE_3D0X2D0]
J16  MICROSD_TF  [TFCARD]
J17  CON40 0.5mm LT  [FPC-CON40-0D5-LT]
J18  CON8 1.25mm LT  [CON8-1D25-LT]
Q2  WPM3401  [SOT23]
R192  10K  [R0402]
R193  100K  [R0402]
R194  100K  [R0402]
R195  100K  [R0402]
R196  100K  [R0402]
R197  100K  [R0402]
R198  100K  [R0402]
R199  10K  [R0402]
R200  0R  [R0402]
R201  0R-0603  [R0603]
R202  0R-0603  [R0603]
R203  0R  [R0402]
R204  10K  [R0402]
R205  0R-0603  [R0603]
R206  0R  [R0402]
R207  0R-0603  [R0603]
R208  0R  [R0402]
R209  0R  [R0402]
R210  1M  [R0402]
R211  0R  [R0402]
R237  1K  [R0402]
R239  1K  [R0402]
TP56  1mm_SMD  [TEST_SMD]
TP57  1mm_SMD  [TEST_SMD]
TP58  1mm_SMD  [TEST_SMD]
TP59  1mm_SMD  [TEST_SMD]
TP60  1mm_SMD  [TEST_SMD]
TP61  1mm_SMD  [TEST_SMD]
TP62  1mm_SMD  [TEST_SMD]
TP63  1mm_SMD  [TEST_SMD]
TP64  1mm_SMD  [TEST_SMD]
TP65  1mm_SMD  [TEST_SMD]
TP66  1mm_SMD  [TEST_SMD]
TP67  1mm_SMD  [TEST_SMD]
TP68  1mm_SMD  [TEST_SMD]
TP69  1mm_SMD  [TEST_SMD]
U21  MS41929  [QFN32_0D5_MS41929]
Y3  27M-2520  [CRY_2D5X2D0]
sheet PAGE13_ETH_PHY
C177  100nF/6.3V  [C0402]
C178  100nF/6.3V  [C0402]
C179  100nF/6.3V  [C0402]
C180  10uF/6.3V  [C0402_E]
C181  100nF/6.3V  [C0402]
C182  10uF/6.3V  [C0402_E]
C183  100nF/6.3V  [C0402]
C184  100nF/6.3V  [C0402]
C185  10uF/6.3V  [C0402_E]
C186  1nF/2KV-1206  [C1206]
C187  100nF/6.3V  [C0402]
C188  10uF/6.3V  [C0402_E]
C189  100nF/6.3V  [C0402]
D16  P3100SC  [SMB]
J19  RJ45 With Led  [RJ45-LED-1A]
R212  33R  [R0402]
R213  2.2R/1%  [R0402]
R214  2.2R/1%  [R0402]
R215  1.5K  [R0402]
R216  2.2R/1%  [R0402]
R217  2.49K/1%  [R0402]
R218  33R  [R0402]
R219  2.2R/1%  [R0402]
R220  33R  [R0402]
R221  33R  [R0402]
R222  10K  [R0402]
R223  10K  [R0402]
R224  300R  [R0402]
R225  10K  [R0402]
R226  0R  [R0402]
R227  10K  [R0402]
R228  75R/1%-0603  [R0603]
R230  10K  [R0402]
R231  300R  [R0402]
R232  10K  [R0402]
R233  10K  [R0402]
R234  10K  [R0402]
R235  10K  [R0402]
R236  0R  [R0402]
R238  2.2R/1%  [R0402]
R240  2.2R/1%  [R0402]
R242  2.2R/1%  [R0402]
R244  2.2R/1%  [R0402]
R245  0R  [R0402]
R246  0R  [R0402]
R247  0R  [R0402]
R298  0R  [R0402]
R299  0R  [R0402]
R314  10K  [R0402]
R315  10K  [R0402]
R316  10K  [R0402]
R317  10K  [R0402]
U22  SZ18201  [QFN32_0D5_SZ18201]
U23  FC1680C  [QFP16_1D27]
sheet PAGE14_RGB_MIPI_LCD
C194  470pF/50V  [C0402]
C195  470pF/50V  [C0402]
C196  1uF/10V  [C0402]
C197  1uF/6.3V  [C0402]
C198  1uF/6.3V  [C0402]
C199  100nF/6.3V  [C0402]
C200  100nF/6.3V  [C0402]
C201  1uF/10V  [C0402]
C202  10uF/10V-0603  [C0603]
C203  1uF/10V  [C0402]
J22  CON50 0.5mm WTXG  [FPC-CON50-0D5-WTXG]
J23  HEADER14 2.54mm MALE  [HEADER7X2M_2D54]
R248  10K  [R0402]
R249  10K  [R0402]
R250  0R  [R0402]
R251  0R-0603  [R0603]
R252  0R-0603  [R0603]
R253  0R  [R0402]
R254  0R  [R0402]
R255  10K  [R0402]
R256  0R  [R0402]
R257  0R  [R0402]
R258  0R  [R0402]
R259  0R  [R0402]
R260  0R-0603  [R0603]
R261  0R  [R0402]
R262  0R  [R0402]
R263  0R  [R0402]
R264  0R  [R0402]
R265  0R  [R0402]
R266  0R  [R0402]
R267  6.19K/1%  [R0402]
R268  0R  [R0402]
R269  0R  [R0402]
R270  0R  [R0402]
R271  0R  [R0402]
R272  0R  [R0402]
R273  0R  [R0402]
R274  0R  [R0402]
R275  0R  [R0402]
R276  10K  [R0402]
R277  0R  [R0402]
R278  0R  [R0402]
R279  0R  [R0402]
U24  SGM3124  [TQFN16_0D5_SGM3124]

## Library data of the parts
C104 C144 C145 = CAP: Capacitor-100pF,+/-5%,C0G,50V-0402; Part Number: 02.0059.00; Part Type: 0402表贴普通电容; 供应商: 国巨 / Murata; 规格型号1: CC0402JRNPO9BN101 / GCM1555C1H101JA16D; 联系人: 谢苏云; 手机: 15900554174; 邮箱: susan.xie@murata.com
C105 C114 C115 C139 C142 C150 C155-C157 C169 C171 C173 = CAP: Capacitor-10uF,+/-20%,X5R,6.3V-0402+; Part Number: 02.0034.00; Part Type: 0402表贴普通电容; 供应商: 国巨 / Murata; 规格型号1: CC0402MRX5R5BB106 / GRM155R60J106ME44D; 联系人: 谢苏云; 手机: 15900554174; 邮箱: susan.xie@murata.com
C106 C137 C147 C149 C162 = CAP: Capacitor-4.7uF,+/-20%,X5R,6.3V-0402; Part Number: 02.0018.00; Part Type: 0402表贴普通电容; 供应商: 国巨 / Murata; 规格型号1: CC0402MRX5R5BB475 / GRM153R60J475ME15D; 联系人: 谢苏云; 手机: 15900554174; 邮箱: susan.xie@murata.com
C107 C212 = CAP: Capacitor-10nF,+/-10%,X7R,25V-0402; Part Number: 02.0012.00; Part Type: 0402表贴普通电容; 供应商: 国巨 / Murata; 规格型号1: CC0402KRX7R8BB103 / GCM155R71E103KA37D; 联系人: 谢苏云; 手机: 15900554174; 邮箱: susan.xie@murata.com
C108 C136 C193 = CAP: Capacitor-1nF,+/-10%,X7R,50V-0402; Part Number: 02.0011.00; Part Type: 0402表贴普通电容; 供应商: 国巨 / Murata; 规格型号1: CC0402KRX7R9BB102 / GCM155R71H102KA37D; 联系人: 谢苏云; 手机: 15900554174; 邮箱: susan.xie@murata.com
C109 C110 C118 C120 C121 C123 C125 C127 C129-C134 C165 C167 C197 C198 = CAP: Capacitor-1uF,+/-10%,X7R,6.3V-0402; Part Number: 02.0076.00; Part Type: 0402表贴普通电容; 供应商: Murata; 规格型号1: GRM155R70J105KA12; 联系人: 谢苏云; 手机: 15900554174; 邮箱: susan.xie@murata.com
C111 C112 = CAP: Capacitor-3.3nF,+/-10%,X7R,50V-0402; Part Number: 02.0042.00; Part Type: 0402表贴普通电容; 供应商: 国巨 / Murata; 规格型号1: CC0402KRX7R9BB332 / GRM155R71H332KA01D; 联系人: 谢苏云; 手机: 15900554174; 邮箱: susan.xie@murata.com
C113 C151 C202 = CAP: Capacitor-10uF,+/-20%,X5R,10V-0603; Part Number: 02.0026.00; Part Type: 0603表贴普通电容; 供应商: YAGEO / Murata; 规格型号1: CC0603MRX5R6BB106 / GRM188R61A106KE47D; 联系人: 谢苏云; 手机: 15900554174; 邮箱: susan.xie@murata.com
D6-D15 = ESD: WILL ESD5451X-2/TR Bidirection 17.5pF Transient Voltage Suppressor; Part Number: 09.0006.00; 供应商: Will; 规格型号1: ESD5451X-2/TR; 联系人: 安志鹏; 手机: 18321800431; 邮箱: an.zhipeng@sh-willsemi.com; Datasheet: ESD5451X.pdf
J9 J10 J13-J15 = CON_2X1: HOLY 1.25mm Pitch 2P LT SMD Connector; Part Number: 04.0001.00; Part Type: 1.25mm立贴连接器; 供应商: 深圳宏利电子; 规格型号1: 1.25mm立贴2P插座; 联系人: 谢素平; 手机: 16717558767; Datasheet: 1.25mm 立贴.pdf
R89-R92 = RES: Resistor-1.1K,+/-5%,1/16W-0402; Part Number: 01.0149.00; Part Type: 0402表贴普通电阻; 供应商: 厚声; 规格型号1: 0402WGJ0112TCE
R93 R94 R97 R103 R108-R119 R125 R126 R144 R145 R147 R148 R154 R155 R157-R162 R164 R182 R184 R187 R200 R203 R206 R208 R226 R236 R245-R247 R250 R253 R254 R256-R259 R261-R266 R268-R275 R277-R279 R298 R299 R313 = RES: Resistor-0R,+/-5%,1/16W-0402; Part Number: 01.0001.00; Part Type: 0402表贴普通电阻; 供应商: 厚声; 规格型号1: 0402WGJ0000TCE
R95 R101 = RES: Resistor-510R,+/-5%,1/16W-0402; Part Number: 01.0082.00; Part Type: 0402表贴普通电阻; 供应商: 厚声; 规格型号1: 0402WGJ0511TCE
R96 R312 = RES: Resistor-20K,+/-1%,1/16W-0402; Part Number: 01.0113.00; Part Type: 0402表贴高精度电阻; 供应商: 厚声; 规格型号1: 0402WGF2002TCE
R98 R100 = RES: Resistor-10K,+/-1%,1/16W-0402; Part Number: 01.0024.00; Part Type: 0402表贴高精度电阻; 供应商: 厚声; 规格型号1: 0402WGF1002TCE
R99 R102 R129-R141 R143 R146 R149 R150 R171 R172 R178 R179 R185 R186 R191 R192 R199 R204 R222 R223 R225 R227 R230 R232-R235 R248 R249 R255 R276 R314-R317 = RES: Resistor-10K,+/-5%,1/16W-0402; Part Number: 01.0023.00; Part Type: 0402表贴普通电阻; 供应商: 厚声; 规格型号1: 0402WGJ0103TCE
R104 R105 = RES: Resistor-68K,+/-1%,1/16W-0402; Part Number: 01.0038.00; Part Type: 0402表贴高精度电阻; 供应商: 厚声; 规格型号1: 0402WGF6802TCE
R106 R107 R122 R127 R128 R163 R166 R183 R189 R201 R202 R205 R207 R251 R252 R260 = RES: Resistor-0R,+/-5%,1/10W-0603; Part Number: 01.0051.00; Part Type: 0603表贴普通电阻; 供应商: 厚声; 规格型号1: 0603WAJ0000T5E
U10 U20 = BUXXTD3WG: ROHM BU25TD3WG 200mA Input-1.7V~6V LDO Regulator; Part Number: 05.0019.00; Part Type: LDO; 供应商: ROHM; 联系人: 李军建; 邮箱: julian-li@rohm.com.cn; Datasheet: buxxtd3wg-e.pdf
U11 U19 = CS8302: 上海智浦欣 CS8302M 3W 单声道 超低EMI 无滤波器 D类音频功放; Part Number: 06.0105.00; Part Type: 功放芯片; 供应商: 上海智浦欣; Datasheet: CS8302M_ch_v1.0.pdf
H1-H6 = MHOLE1: MechanicalHole φ4.2mmX3.2mm Drill 3.0mmX2.0mm; Part Number: AB.0001.00; Part Type: MechanicalHole
J11 = FPCCON_18X2: HOLY 0.5mm pitch FPC LT 36 Pin Connector; Part Number: 04.0014.00; Part Type: 0.5mm立贴FPC连接器; 供应商: 深圳宏利电子; 规格型号1: FPC0.5mm-36P立贴正位; 联系人: 谢素平; 手机: 16717558767; Datasheet: 0.5mm立式正位全包.pdf
J12 = FPCCON_15x2: HOLY 0.5mm pitch FPC LT 30 Pin Connector; Part Number: 04.0011.00; Part Type: 0.5mm立贴FPC连接器; 供应商: 深圳宏利电子; 规格型号1: FPC0.5mm-30P立贴正位; 联系人: 谢素平; 手机: 16717558767; Datasheet: 0.5mm立式正位全包.pdf
TP30 TP32 TP33 TP35 TP46 TP48-TP69 = TP: SMD Test Point φ1mm; Part Number: AA.0001.00; Part Type: Test Point
TP31 TP34 TP36-TP44 TP47 = TP: SMD Test Point φ0.5mm; Part Number: AA.0006.00; Part Type: Test Point
C116 C117 C122 C124 C126 C128 C138 C140 C141 C143 C146 C148 C158 C160 C161 C163 C164 C166 C168 C170 C172 C174 C177-C179 C181 C183 C184 C187 C189 C199 C200 = CAP: Capacitor-100nF,+/-10%,X7R,6.3V-0402; Part Number: 02.0075.00; Part Type: 0402表贴普通电容; 供应商: Murata; 规格型号1: GRM155R70J104KA01D; 联系人: 谢苏云; 手机: 15900554174; 邮箱: susan.xie@murata.com
C119 = CAP: Capacitor-8.2pF,+/-0.25pF,C0G,50V-0402; Part Number: 02.0047.00; Part Type: 0402表贴普通电容; 供应商: 国巨 / Murata; 规格型号1: CC0402CRNPO9BN8R2 / GRM1555C1H8R2CA01D; 联系人: 谢苏云; 手机: 15900554174; 邮箱: susan.xie@murata.com
FB11 FB12 FB17 = BEAD: Murata BLM15PX221SN1D Z=220ohm@100MHz 1.4A 0.1ohm 25%; Part Number: 03.1006.00; Part Type: 0402表贴磁珠; 供应商: Murata; 规格型号1: BLM15PX221SN1D; 联系人: 谢苏云; 手机: 15900554174; 邮箱: susan.xie@murata.com; Datasheet: BLM15.pdf
FB13-FB16 = BEAD: Murata BLM15HG102SN1D Z=1000ohm@100MHz 250mA 1.1ohm 25%; Part Number: 03.1001.00; Part Type: 0402表贴磁珠; 供应商: Murata; 规格型号1: BLM15HG102SN1D; 联系人: 谢苏云; 手机: 15900554174; 邮箱: susan.xie@murata.com; Datasheet: BLM15HG.pdf
R142 R193-R198 = RES: Resistor-100K,+/-5%,1/16W-0402; Part Number: 01.0041.00; Part Type: 0402表贴普通电阻; 供应商: 厚声; 规格型号1: 0402WGJ0104TCE
U12 = NCEMAHBD-08G: FORESEE NCEMAHBD-08G 8GB 8xIOs e-MMC 153Ball 0.5mmPitch; Part Number: 06.0112.00; Part Type: EMMC; 供应商: FORESEE; Datasheet: eMMC_NCEMAHBD-08G FORESEE_SPEC.pdf
U13-U16 = MSM261D4030H1: 敏芯微 MSM261D4030H1CPM PDM digital output MEMS microphone with Multi-modes; Part Number: 07.1010.02; Part Type: DMIC; 供应商: 敏芯微; Datasheet: MSM261D4030H1CPM_V1.2-ENG.pdf
C135 = CAP: Capacitor-2.2uF,+/-10%,X5R,10V-0402; Part Number: 02.0017.00; Part Type: 0402表贴普通电容; 供应商: 国巨 / Murata; 规格型号1: CC0402KRX5R6BB225 / GRM155R61A225KE95D; 联系人: 谢苏云; 手机: 15900554174; 邮箱: susan.xie@murata.com
C152 = CAP: Capacitor-100nF,+/-10%,X7R,10V-0402; Part Number: 02.0075.00; Part Type: 0402表贴普通电容; 供应商: Murata; 供应商1: Eyang; 规格型号1: GRM155R71A104KA01D; 联系人: 谢苏云; 联系人1: 何俊; 手机: 15900554174; 手机1: 18317187178; 邮箱: susan.xie@murata.com; 邮箱1: hejunxs@szeyang.com
C153 C154 = CAP: Capacitor-1uF,+/-10%,X5R,16V-0402; Part Number: 02.0016.00; Part Type: 0402表贴普通电容; 供应商: 国巨 / Murata; 规格型号1: CC0402KRX5R7BB105 / GRM155R61C105KA12D; 联系人: 谢苏云; 手机: 15900554174; 邮箱: susan.xie@murata.com
R168-R170 R174 R175 = RES: Resistor-4.7K,+/-5%,1/16W-0402; Part Number: 01.0019.00; Part Type: 0402表贴普通电阻; 供应商: 厚声; 规格型号1: 0402WGJ0472TCE
R173 R237 R239 = RES: Resistor-1K,+/-5%,1/16W-0402; Part Number: 01.0014.00; Part Type: 0402表贴普通电阻; 供应商: 厚声; 规格型号1: 0402WGJ0102TCE
R176 R177 R180 R181 = RES: Resistor-2.2K,+/-5%,1/16W-0402; Part Number: 01.0017.00; Part Type: 0402表贴普通电阻; 供应商: 厚声; 规格型号1: 0402WGJ010JTCE
R188 R190 = RES: Resistor-240R,+/-1%,1/16W-0402; Part Number: 01.0010.00; Part Type: 0402表贴高精度电阻; 供应商: 厚声; 规格型号1: 0402WGF2400TCE
U17 = AK7755EN: AKM AK7755EN DSP with Mono ADC Stereo CODEC + Mic/Lineout Amp; Part Number: 06.0138.00; Part Type: Codec芯片; 供应商: AKM; Datasheet: ak7755en-en-datasheet.pdf
U18 = BUXXTD3WG: ROHM BU33TD3WG 200mA Input 1.7V~6V LDO Regulator; Part Number: 05.0016.00; Part Type: LDO; 供应商: ROHM; 联系人: 李军建; 邮箱: julian-li@rohm.com.cn; Datasheet: buxxtd3wg-e.pdf
C159 = CAP: Capacitor-22uF,+/-20%,X5R,10V-0805; Part Number: 02.0076.00; Part Type: 0805表贴普通电容; 供应商: 华新科 / Murata; 规格型号1: 0805X226M100CT / GRM21BR61A226ME51L; 联系人: 谢苏云; 手机: 15900554174; 邮箱: susan.xie@murata.com
C175 C176 = CAP: Capacitor-12pF,+/-5%,C0G,50V-0402; ID: 8; Part Number: 02.0006.00; Part Type: 0402表贴普通电容; 供应商: 国巨 / Murata; 供应商2: Murata; 规格型号1: CC0402JRNPO9BN120 / GCM1555C1H120JA16D; 联系人: 谢苏云; 联系人2: 吴铭; 手机: 15900554174; 手机2: 13761466262; 邮箱: susan.xie@murata.com; 邮箱2: cherry.wu@murata.com
J16 = MMC_SD: TF CARD SOCKET; Part Number: 10.0003.00; Part Type: TF Card; 规格型号1: TF卡座; Datasheet: TF卡座.jpg
J17 = FPCCON_20X2: HOLY 0.5mm pitch FPC LT 40 Pin Connector; Part Number: 04.0015.00; Part Type: 0.5mm立贴FPC连接器; 供应商: 深圳宏利电子; 规格型号1: FPC0.5mm-40P立贴正位; 联系人: 谢素平; 手机: 16717558767; Datasheet: 0.5mm立式正位全包.pdf
J18 = CON_8X1: HOLY 1.25mm Pitch 8P LT SMD Connector; Part Number: 04.0008.00; Part Type: 1.25mm立贴连接器; 供应商: 深圳宏利电子; 规格型号1: 1.25mm立贴8P插座; 联系人: 谢素平; 手机: 16717558767; Datasheet: 1.25mm 立贴.pdf
Q2 = P_MOS: WILL WPM3401 P-Channel MOSFET; Part Number: 09.0008.00; Part Type: MOS管; 供应商: Will; 联系人: 安志鹏; 手机: 18321800431; 邮箱: an.zhipeng@sh-willsemi.com; Datasheet: WPM340_datasheet.pdf
R209 R211 = RES: Resistor-0R,+/-5%,1/16W-0402; ID: 18; Part Number: 01.0001.00; Part Type: 0402表贴普通电阻; 供应商: 厚声; 供应商1: Eyang; 规格型号1: 0402WGJ0000TCE; 联系人1: 何俊; 手机1: 18317187178; 邮箱1: hejunxs@szeyang.com
R210 = RES: Resistor-1M,+/-5%,1/16W-0402; ID: 49; Part Number: 01.0049.00; Part Type: 0402表贴普通电阻; 供应商: 厚声; 供应商1: Eyang; 规格型号1: 0402WGJ0105TCE; 联系人1: 何俊; 手机1: 18317187178; 邮箱1: hejunxs@szeyang.com
U21 = MS41929: 瑞盟 MS41929 双通道超低噪声256细分微步进低压电机驱动芯片; Part Number: 06.0113.00; Part Type: 驱动芯片; 供应商: 瑞盟; Datasheet: MS41929.pdf
Y3 = XTAL_P4: Murata XRCGB27M000F2P01R0 Crystal total ±45ppm 8pF; Part Number: 08.0019.00; Part Type: Crystal; 供应商: Murata; 规格型号1: XRCGB27M000F2P01R0; 联系人: 谢苏云; 手机: 15900554174; 邮箱: susan.xie@murata.com
C180 C182 C185 C188 = CAP: Capacitor-10uF,+/-20%,X5R,6.3V-0402+; Part Number: 02.0034.00; Part Type: 0402表贴普通电容; 供应商: YAGEO / Murata; 供应商2: Murata; 规格型号1: CC0402MRX5R5BB106 / GRM155R60J106ME44D; 联系人: 谢苏云; 联系人2: 吴铭; 手机: 15900554174; 手机2: 13761466262; 邮箱: susan.xie@murata.com; 邮箱2: cherry.wu@murata.com
C186 = CAP: Capacitor-1nF,+/-10%,X7R,2KV-1206; Part Number: 02.0030.00; Part Type: 1206表贴高压电容; 供应商: YAGEO / Murata; 规格型号1: CC1206KKX7RDBB102 / GR431BR7LA102KW66L; 联系人: 谢苏云; 手机: 15900554174; 邮箱: susan.xie@murata.com
D16 = P3100: BrightKing P3100SC 防雷管 半导体放电管 10/700us_6000V; Part Number: 09.0010.00; Part Type: 防护二极管; Datasheet: P3100.pdf
J19 = RJ45_1x1_LED: RJ45-LED-1A Ethernet Connector With LED; Part Number: 10.0001.00; Part Type: 网口连接座; 规格型号1: RJ45带灯; Datasheet: PCB-937带灯.pdf
R212 R218 R220 R221 = RES: Resistor-33R,+/-5%,1/16W-0402; Part Number: 01.0005.00; Part Type: 0402表贴普通电阻; 供应商: 厚声; 规格型号1: 0402WGJ0330TCE
R213 R214 R216 R219 R238 R240 R242 R244 = RES: Resistor-2.2R,+/-1%,1/16W-0402; Part Number: 01.0126.00; Part Type: 0402表贴高精度电阻; 供应商: 厚声; 规格型号1: 0402WGF220KTCE
R215 = RES: Resistor-1.5K,+/-5%,1/16W-0402; Part Number: 01.0085.00; Part Type: 0402表贴普通电阻; 供应商: 厚声; 规格型号1: 0402WGJ0152TCE
R217 = RES: Resistor-2.49K,+/-1%,1/16W-0402; Part Number: 01.0134.00; Part Type: 0402表贴高精度电阻; 供应商: 厚声; 规格型号1: 0402WGF2491TCE
R224 R231 = RES: Resistor-300R,+/-5%,1/16W-0402; Part Number: 01.0011.00; Part Type: 0402表贴普通电阻; 供应商: 厚声; 规格型号1: 0402WGJ0301TCE
R228 = RES: Resistor-75R,+/-1%,1/10W-0603; Part Number: 01.0052.00; Part Type: 0603表贴高精度电阻; 供应商: 厚声; 规格型号1: 0603WAF750JT5E
U22 = SZ18201_1: Motor Comm SZ18201 Single Chip 10/100M Ethernet Phyceiver with Auto MDIX; Part Number: 06.0123.00; Part Type: ETH Phy 芯片; 供应商: Motor Comm; Datasheet: SZ18201_2021-05-28.PDF
U23 = FC1680C: IC-FLY FC1680C 10/100 Small Package Transformer module; Part Number: 06.0010.00; Part Type: 网络变压器; 供应商: 上海飞芯电子; 联系人: 刘经纬; 手机: 18621560356; Datasheet: FC1680C.20120213.pdf
C194 C195 = CAP: Capacitor-470pF,+/-10%,X7R,50V-0402; Part Number: 02.0010.00; Part Type: 0402表贴普通电容; 供应商: YAGEO / Murata; 规格型号1: CC0402KRX7R9BB471 / GCM155R71H471KA37D; 联系人: 谢苏云; 手机: 15900554174; 邮箱: susan.xie@murata.com
C196 C201 C203 = CAP: Capacitor-1uF,+/-10%,X5R,10V-0402; Part Number: 02.0016.00; Part Type: 0402表贴普通电容; 供应商: Murata; 规格型号1: GRT155R61A105KE01D; 联系人: 谢苏云; 手机: 15900554174; 邮箱: susan.xie@murata.com
J22 = FPCCON_50_LCD: HOLY 0.5mm pitch FPC WTXG 50 Pin Connector; Part Number: 04.0103.00; Part Type: 2.8寸LCD屏FPC连接器; 供应商: 深圳宏利电子; 规格型号1: 0.5mm-50P卧贴翻盖下接FPC连接器; 联系人: 谢素平; 手机: 16717558767; Datasheet: WZ028QVFBA006-RT 规格书.pdf
J23 = HEADER_7x2: HEADER 7X2 2.54mm MALE; Part Number: 04.0037.00; Part Type: 2.54mm双排插针; 规格型号1: 2.54mm 2X7双排排针
R267 = RES: Resistor-6.19K,+/-1%,1/16W-0402; Part Number: 01.0022.00; Part Type: 0402表贴高精度电阻; 供应商: 厚声; 规格型号1: 0402WGF6191TCE
U24 = SGM3124: SGMICRO SGM3124 White LED Charge Pump Current Source with PWM Brightness Control; Part Number: 06.0064.00; Part Type: 驱动芯片; 供应商: SGMICRO; 规格型号1: SGM3124YTQ16G/TR; 联系人: 王哲; 手机: 18406666893; 邮箱: jayden_wang@sg-micro.com; Datasheet: SGM3124 REV.A.1_20130111.pdf

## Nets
AVDD33: C188.1 C189.1 R235.2 R236.1 U22.7(AVDD33_1)
GND: C106.2 C107.2 C108.2 C109.2 C110.2 C111.2 C113.2 C114.2 C115.2 C116.2 C117.2 C118.2 C119.2 C120.2 C121.2 C122.2 C123.2 C124.2 C125.2 C126.2 C127.2 C128.2 C134.2 C135.2 C136.2 C137.2 C138.2 C139.2 C140.2 C141.2 C142.2 C143.2 C146.2 C147.2 C148.2 C149.2 C150.2 C151.2 C152.2 C153.1 C155.2 C156.2 C157.2 C158.2 C159.2 C160.2 C161.2 C162.2 C163.2 C165.2 C166.2 C167.2 C168.2 C169.2 C170.2 C171.2 C172.2 C173.2 C174.2 C175.1 C176.1 C177.1 C178.1 C179.1 C180.2 C181.2 C182.2 C183.2 C184.2 C185.2 C186.1 C187.2 C188.2 C189.2 C193.1 C196.2 C197.2 C198.2 C199.2 C200.2 C201.2 C202.2 C203.2 C212.1 D6.1(ANODE) D7.1(ANODE) D8.1(ANODE) D9.1(ANODE) D10.1(ANODE) D11.1(ANODE) D12.1(ANODE) D13.1(ANODE) D14.1(ANODE) D15.1(ANODE) D16.2 H1.1(A) H2.1(A) H3.1(A) H4.1(A) H5.1(A) H6.1(A) J9.3(S1) J9.4(S2) J10.3(S1) J10.4(S2) J11.7 J11.10 J11.15 J11.20 J11.27 J11.29 J11.37(S1) J11.38(S2) J12.1 J12.4 J12.7 J12.10 J12.13 J12.16 J12.21 J12.23 J12.27 J12.31(S1) J12.32(S2) J13.3(S1) J13.4(S2) J14.3(S1) J14.4(S2) J15.3(S1) J15.4(S2) J16.6(VSS2) J16.10(GND_2) J16.11(GND_1) J16.12(PAD1) J16.13(PAD2) J17.1 J17.4 J17.8 J17.9 J17.19 J17.32 J17.39 J17.41(S1) J17.42(S2) J18.9(S1) J18.10(S2) J19.9(SH1) J19.10(SH2) J19.12(CON_PIN[11]) J19.14(CON_PIN[13]) J22.1(GND) J22.23(DB0) J22.24(DB1) J22.25(DB2) J22.26(DB3) J22.27(DB4) J22.28(DB5) J22.29(DB6) J22.30(DB7) J22.31(DB8) J22.32(DB9) J22.42(GND_2) J22.50(GND_3) J22.51(S1) J22.52(S2) J23.4 J23.13 J23.14 R89.2 R98.1 R100.2 R102.2 R143.1 R146.1 R149.1 R150.1 R162.1 R170.1 R175.1 R176.2 R177.2 R186.2 R199.1 R217.2 R223.2 R225.1 R226.1 R230.2 R233.2 R248.2 R255.2 R267.1 R276.2 R315.2 R317.2 U10.2(GND) U11.7(GND) U12.A6(VSS_1) U12.C4(VSSQ_1) U12.E7(VSS_2) U12.G5(VSS_3) U12.H10(VSS_4) U12.J5(VSS_5) U12.K8(VSS_6) U12.N2(VSSQ_2) U12.N5(VSSQ_3) U12.P4(VSSQ_4) U12.P6(VSSQ_5) U13.5(GND1) U13.6(GND2) U13.7(GND3) U13.8(GND4) U14.5(GND1) U14.6(GND2) U14.7(GND3) U14.8(GND4) U15.5(GND1) U15.6(GND2) U15.7(GND3) U15.8(GND4) U16.5(GND1) U16.6(GND2) U16.7(GND3) U16.8(GND4) U17.2(AVSS1) U17.13(DVSS1) U17.25(DVSS2) U17.30(AVSS2) U17.37(E-PAD) U18.2(GND) U19.7(GND) U20.2(GND) U21.6(GND5) U21.12(MGNDB) U21.18(MGNDA) U21.22(GNDD) U21.33(E-PAD) U22.33(GND) U24.7(PGND) U24.14(GND) U24.17(POWER_PAD) Y3.2 Y3.4 ; also on sheet 3 4 5 6 7 15
VCC_3V3: C110.1 C159.1 C160.1 C161.1 C162.1 C163.1 C164.1 C180.1 C181.1 FB11.1 FB12.1 FB13.2 FB14.2 FB15.2 FB16.2 J17.2 J17.3 J17.5 J17.6 J17.7 Q2.2(SOURCE) R99.1 R107.2 R128.1 R163.2 R192.2 R198.1 R201.2 R204.1 R215.1 R222.1 R227.1 R232.1 R234.1 R236.2 R249.2 R251.1 R252.1 R257.2 R314.1 R316.1 U10.1(Vin) U22.14(DVDD33_1) ; also on sheet 3 5 7 15
VCC_5V: C151.1 C202.1 C203.1 J23.1 J23.2 R106.2 R122.2 R127.1 R185.2 R189.2 R202.2 R205.2 R207.2 R260.2 U18.1(Vin) ; also on sheet 3 5
VCCQ_3V3: C115.1 C116.1 FB12.2 R133.1 R134.1 R135.1 R136.1 R137.1 R138.1 R139.1 R140.1 R141.1 R142.2 U12.C6(VCCQ_5) U12.M4(VCCQ_1) U12.N4(VCCQ_2) U12.P3(VCCQ_3) U12.P5(VCCQ_4)
VDD5: C168.1 R207.1 U21.4(VDD5)
VDDMSC0: C165.1 C166.1 J16.4(VDD) Q2.3(DRAIN) R193.1 R194.1 R195.1 R196.1 R197.1 R199.2
AK7755_AVDD: C139.1 C140.1 C141.1 C157.1 FB17.2 R183.2 R191.2 U17.21(AVDD1) U17.36(AVDD3) U20.1(Vin)
AK7755_AVDD2: C137.1 C138.1 FB17.1 U17.29(AVDD2)
AK7755_AVDRV: C134.1 U17.24(DVDD/AVDRV)
AK7755_IOVDD: C142.1 C143.1 R163.1 R166.2 R168.1 R169.1 R171.2 R172.2 R174.2 U17.12(TVDD)
AK7755_LDOE: R166.1 U17.23(LDOE)
AK7755_LIN: C130.1 TP50.1
AK7755_PDN: R171.1 R173.1 ; also on sheet 7
AK7755_VCOM: C135.1 U17.1(VCOM)
BT656_D0_PD00: J23.5 R254.2
BT656_D1_PD01: J23.6 R256.2
BT656_D2_PD02: J23.7 R259.2
BT656_D3_PD03: J23.8 R263.2
BT656_D4_PD04: J23.9 R264.2
BT656_D5_PD05: J23.10 R268.2
BT656_D6_PD06: J23.11 R270.2
BT656_D7_PD07: J23.12 R272.2
BT656_PCLK_PD08: J23.3 R274.2
CLK_CTRL: R232.2 R233.1 U22.12(RXD[3]/CLK_CTL)
CLKO: TP54.1 U17.9(CLKO)
CSI_CLKN_DVP_D4: R118.1 R119.1 TP39.1 ; also on sheet 6
CSI_CLKP_DVP_D5: R116.1 R117.1 TP38.1 ; also on sheet 6
CSI_DATAN0_DVP_D0: R110.1 R111.1 TP34.1 ; also on sheet 6
CSI_DATAN1_DVP_D2: R114.1 R115.1 TP37.1 ; also on sheet 6
CSI_DATAP0_DVP_D1: R108.1 R109.1 TP31.1 ; also on sheet 6
CSI_DATAP1_DVP_D3: R112.1 R113.1 TP36.1 ; also on sheet 6
DMIC_CLK_PB28: R144.2 R147.2 R154.2 R157.2 ; also on sheet 6
DMIC_DAT0_PB29: R145.2 R148.2 ; also on sheet 6
DMIC_DAT1_PB30: R155.2 R158.2 ; also on sheet 6
DVP_3V3: J11.1 J11.2 R107.1
DVP_5V: J11.34 J11.35 J11.36 R122.1
DVP_D0: J11.11 R111.2
DVP_D1: J11.12 R109.2
DVP_D2: J11.13 R115.2
DVP_D3: J11.14 R113.2
DVP_D4: J11.16 R119.2
DVP_D5: J11.17 R117.2
DVP_D6: J11.18 ; also on sheet 6
DVP_D7: J11.19 ; also on sheet 6
DVP_D8: J11.21 ; also on sheet 6
DVP_D9: J11.22 ; also on sheet 6
DVP_HSYNC: J11.8 TP33.1 ; also on sheet 6
DVP_MCLK_PA15: J11.28 R126.2 TP30.1
DVP_PCLK: J11.26 TP32.1 ; also on sheet 6
DVP_VSYNC: J11.9 TP35.1 ; also on sheet 6
E_MICBIAS_2V5: C156.1 R182.2 R184.2 U20.5(Vout)
EMMC_3V3: C114.1 C117.1 FB11.2 U12.E6(VCC_1) U12.F5(VCC_2) U12.J10(VCC_3) U12.K9(VCC_4)
EMMC_CLK: C119.1 U12.M6(CLK) ; also on sheet 7
EMMC_CMD: R141.2 U12.M5(CMD) ; also on sheet 7
EMMC_D0: R133.2 U12.A3(DAT0) ; also on sheet 7
EMMC_D1: R134.2 U12.A4(DAT1) ; also on sheet 7
EMMC_D2: R135.2 U12.A5(DAT2) ; also on sheet 7
EMMC_D3: R136.2 U12.B2(DAT3) ; also on sheet 7
EMMC_D4: R137.2 U12.B3(DAT4)
EMMC_D5: R138.2 U12.B4(DAT5)
EMMC_D6: R139.2 U12.B5(DAT6)
EMMC_D7: R140.2 U12.B6(DAT7)
EMMC_DS: TP47.1 U12.H5(DS)
EMMC_RST: C118.1 R142.1 U12.K5(RSTN) ; also on sheet 6
EMMC_VDDI: C120.1 U12.C2(VDDI)
GMAC_MDC: U22.22(MDC) ; also on sheet 6
GMAC_MDIO: R215.2 U22.23(MDIO) ; also on sheet 6
GMAC_NRST_PB28: R298.1 ; also on sheet 6
GMAC_PHY_CLK: U22.31(XTAL_IN) ; also on sheet 6
GMAC_RXD0: R220.1 ; also on sheet 6
GMAC_RXD1: R221.1 R222.2 R223.1 ; also on sheet 6
GMAC_RXDV: R218.1 ; also on sheet 6
GMAC_TXCLK: R212.1 ; also on sheet 6
GMAC_TXD0: U22.16(TXD[0]) ; also on sheet 6
GMAC_TXD1: U22.17(TXD[1]) ; also on sheet 6
GMAC_TXEN: U22.20(TXEN) ; also on sheet 6
HPOUTL: C112.2 ; also on sheet 5
I2C0_MIPI_DVP_SCK: J11.3 J12.20 TP41.1 ; also on sheet 6
I2C0_MIPI_DVP_SDA: J11.6 J12.19 TP40.1 ; also on sheet 6
I2C1_SCK_CODEC: R169.2 U17.18(SCLK/SCL) ; also on sheet 7
I2C1_SDA_CODEC: R168.2 U17.17(SO/SDA) ; also on sheet 7
I2C2_SID: R174.1 R175.2 U17.20(CSN/CAD/MATSEL)
I2S_DAC_BCLK: R160.1 ; also on sheet 7
I2S_DAC_BCLK_PC15: R160.2 U17.8(BICK)
I2S_DAC_LRCK: R159.1 ; also on sheet 7
I2S_DAC_LRCK_PC16: R159.2 U17.7(LRCK)
I2S_DAC_MCLK: U17.11(XTI) ; also on sheet 7
I2S_SDTI: R161.1 ; also on sheet 7
I2S_SDTI_PC18: R161.2 U17.16(SDOUT1/EEST)
I2S_SDTO: R164.1 ; also on sheet 7
I2S_SDTO_PC17: R164.2 U17.4(SDIN2/JX1)
I_MICBIAS_2V5: C109.1 R93.2 U10.5(Vout)
IM0: J22.12(IM0) R249.1
IM1: J22.11(IM1) R255.1
IM2: J22.10(IM2) R248.1
INN1: C131.2 U17.33(IN2/INN1/DMCLK1)
INN2: C133.2 U17.31(IN4/INN2/DMCLK2)
INP1: C129.2 U17.34(IN1/INP1/DMDAT1)
INP2: C132.2 U17.32(IN3/INP2/DMDAT2)
IRCUT_IN1: TP62.1 U21.2(IN1)
IRCUT_IN2: TP63.1 U21.3(IN2)
LED0: R246.1 ; also on sheet 6
LED1: R299.1 ; also on sheet 6
LED2: TP65.1 U21.21(LED2)
LED11: TP64.1 U21.20(LED1)
LIN: C130.2 U17.35(LIN)
LR1: R129.2 R143.2 U13.2(L/R)
LR2: R130.2 R146.2 U14.2(L/R)
LR3: R131.2 R149.2 U15.2(L/R)
LR4: R132.2 R150.2 U16.2(L/R)
M_F_A+: J18.7 U21.14(OUTB2)
M_F_A-: J18.8 U21.16(OUTB1)
M_F_B+: J18.1 U21.17(OUTA2)
M_F_B-: J18.2 U21.19(OUTA1)
M_OSCIN: R209.2 U21.24(OSCIN)
M_OSCOUT: R211.2 U21.23(OSCOUT)
M_RSTB: C167.1 R204.2 U21.1(RSTB) ; also on sheet 7
M_VD_FZ: U21.30(VD_FZ) ; also on sheet 7
M_Z_A+: J18.5 U21.8(OUTD2)
M_Z_A-: J18.6 U21.10(OUTD1)
M_Z_B+: J18.4 U21.11(OUTC2)
M_Z_B-: J18.3 U21.13(OUTC1)
MDI_RN: R219.2 R244.2 U23.1(TD+/RD+)
MDI_RP: R216.2 R242.2 U23.3(TD-/RD-)
MDI_TN: R214.2 R240.2 U23.6(RD+/TD+)
MDI_TP: R213.2 R238.2 U23.8(RD-/TD-)
MDVDD: C173.1 C174.1 R201.1 U21.25(DVDD)
MICBIAS: R94.2 ; also on sheet 5
MICN1: C131.1 C144.1 D11.2(CATHODE) J13.1 R176.1 R178.1
MICN2: C133.1 C145.1 D13.2(CATHODE) J14.1 R177.1 R179.1
MICNL: C104.1 D7.2(CATHODE) J9.1 R90.1 R313.2 ; also on sheet 5
MICP1: C129.1 C144.2 D10.2(CATHODE) J13.2 R178.2 R180.2
MICP2: C132.1 C145.2 D12.2(CATHODE) J14.2 R179.2 R181.2
MICPL: C104.2 D6.2(CATHODE) J9.2 R91.2 R97.2 ; also on sheet 5
MIPI1_2LANE_3V3: J12.30 R128.2
MIPI1_2LANE_5V: J12.28 J12.29 R127.2
MIPI_DVP_IRCUTN_PB18: J11.31 J12.25 ; also on sheet 6
MIPI_DVP_IRCUTP_PB17: J11.32 J12.24 ; also on sheet 6
MIPI_DVP_MCLK: R125.1 R126.1 TP42.1 ; also on sheet 6
MIPI_DVP_PWDN_PA19: J11.25 J12.26 TP44.1 ; also on sheet 6
MIPI_DVP_RESET: J11.33 J12.18 TP43.1 ; also on sheet 6
MIPI_MCLK_PA15: J12.22 R125.2 TP46.1
MIPI_RX_2LANE_CLKN0: J12.2 R118.2
MIPI_RX_2LANE_CLKP0: J12.3 R116.2
MIPI_RX_2LANE_DN0: J12.5 R110.2
MIPI_RX_2LANE_DN1: J12.8 R114.2
MIPI_RX_2LANE_DP0: J12.6 R108.2
MIPI_RX_2LANE_DP1: J12.9 R112.2
MSC0_CLK_PB04: J16.5(CLK) TP61.1 ; also on sheet 6
MSC0_CMD_PB05: J16.3(CMD) R197.2 TP60.1 ; also on sheet 6
MSC0_D0_PB00: J16.7(DAT0) R193.2 TP56.1 ; also on sheet 6
MSC0_D1_PB01: J16.8(DAT1) R194.2 TP57.1 ; also on sheet 6
MSC0_D2_PB02: J16.1(DAT2) R195.2 TP58.1 ; also on sheet 6
MSC0_D3_PB03: J16.2(DAT3) R196.2 TP59.1 ; also on sheet 6
MVCCA: C169.1 C170.1 R202.1 U21.15(MVCCA)
MVCCB: C171.1 C172.1 R205.1 U21.9(MVCCB)
OUT2_R: TP48.1 U17.26(OUT2)
OUT3_MIXER: TP49.1 U17.27(OUT3)
OUTE1: TP66.1 U21.7(OUTE1)
OUTE2: TP69.1 U21.5(OUTE2)
PHY_ACTA: R224.2 R245.2 R246.2
PHY_LED0: R245.1 R314.2 R315.1 U22.24(LED0/PHYAD[0])
PHY_LED1: R247.1 R316.2 R317.1 U22.25(LED1/PHYAD[1])
PHY_LINKA: R231.2 R247.2 R299.2
PULSE1: TP67.1 U21.31(PULSE1)
PULSE2: TP68.1 U21.32(PULSE2)
RD_N: R244.1 ; also on sheet 6
RD_P: R242.1 ; also on sheet 6
RX+: J19.3(CON_PIN[2]) U23.14(TX-/RX-)
RX-: J19.6(CON_PIN[5]) U23.16(TX+/RX+)
RX_N1: R219.1 U22.6(TRXN1)
RX_P1: R216.1 U22.5(TRXP1)
RXDV: R227.2 R230.1 U22.8(RXDV)
SD0_CD_N_PB27: J16.9(CD) R192.1 R237.1 ; also on sheet 6
SD_PWR_EN_N: R239.1 ; also on sheet 6
SDIN1: R162.2 U17.5(SDIN1/JX0)
SDIO_WIFI_CLK_PC02: J17.24 ; also on sheet 7
SDIO_WIFI_CMD_PC03: J17.34 ; also on sheet 7
SDIO_WIFI_D0_PC04: J17.23 ; also on sheet 7
SDIO_WIFI_D1_PC05: J17.35 ; also on sheet 7
SDIO_WIFI_D2_PC06: J17.33 ; also on sheet 7
SDIO_WIFI_D3_PC07: J17.36 ; also on sheet 7
SDIO_WIFI_EN_PC09: J17.16 ; also on sheet 7
SDOUT2: TP51.1 U17.15(SDOUT2/JX3/MAT0)
SDOUT3: TP52.1 U17.14(SDOUT3/JX2/MAT1)
SLCD_BLEN: R276.1 U24.15(EN1) U24.16(EN2) ; also on sheet 7
SLCD_BT656_D0: R253.1 R254.1 ; also on sheet 7
SLCD_BT656_D1: R250.1 R256.1 ; also on sheet 7
SLCD_BT656_D2: R258.1 R259.1 ; also on sheet 7
SLCD_BT656_D3: R261.1 R263.1 ; also on sheet 7
SLCD_BT656_D4: R262.1 R264.1 ; also on sheet 7
SLCD_BT656_D5: R266.1 R268.1 ; also on sheet 7
SLCD_BT656_D6: R269.1 R270.1 ; also on sheet 7
SLCD_BT656_D7: R271.1 R272.1 ; also on sheet 7
SLCD_CS: R277.1 ; also on sheet 7
SLCD_CS_PD10: J22.14(CS) R277.2
SLCD_D0_PD00: J22.33(DB10) R253.2
SLCD_D1_PD01: J22.34(DB11) R250.2
SLCD_D2_PD02: J22.35(DB12) R258.2
SLCD_D3_PD03: J22.36(DB13) R261.2
SLCD_D4_PD04: J22.37(DB14) R262.2
SLCD_D5_PD05: J22.38(DB15) R266.2
SLCD_D6_PD06: J22.39(DB16) R269.2
SLCD_D7_PD07: J22.40(DB17) R271.2
SLCD_DC: R278.1 ; also on sheet 7
SLCD_DC_PD11: J22.15(RS_SPI-RS) R278.2
SLCD_IOVDD: C198.1 C200.1 J22.6(IOVCC_1) J22.7(IOVCC_2) R251.2
SLCD_LEDA: C201.1 J22.43(LEDA) U24.8(VOUT)
SLCD_LEDK: J22.44(LEDK1) J22.45(LEDK2) J22.46(LEDK3) J22.47(LEDK4) J22.48(LEDK5) J22.49(LEDK6) R265.2 U24.5(D2) U24.6(D1)
SLCD_RDY: R279.1 ; also on sheet 7
SLCD_RDY_PD12: J22.17(RD) R257.1 R279.2
SLCD_RST_PD09: J22.13(RESET) R275.2
SLCD_TE: R275.1 ; also on sheet 7
SLCD_VCI: C197.1 C199.1 J22.8(VCI_1) J22.9(VCI_2) R252.2
SLCD_WR_BT656_PCLK: R273.1 R274.1 ; also on sheet 7
SLCD_WR_PD08: J22.16(WR_SPI-SCL) R273.2
SPEAK_EN_PB31: R103.1 R187.1 ; also on sheet 6
SPI1_CLK: R206.1 ; also on sheet 7
SPI1_CLK_PA22: R206.2 U21.26(SCK)
SPI1_CS: R208.1 ; also on sheet 7
SPI1_CS_PA29: R208.2 U21.27(CS)
SPI1_DR: R203.1 ; also on sheet 7
SPI1_DR_PA21: R203.2 U21.28(SOUT)
SPI1_DT: R200.1 ; also on sheet 7
SPI1_DT_PA20: R200.2 U21.29(SIN)
SPK_OUTL: C154.1 U17.28(OUT1)
SPKOUT_N: D8.2(CATHODE) J10.1 R101.1 U11.8(VO-)
SPKOUT_P: D9.2(CATHODE) J10.2 R95.1 U11.5(VO+)
STO: TP55.1 U17.6(STO/RDY)
TD_N: R240.1 ; also on sheet 6
TD_P: R238.1 ; also on sheet 6
TX+: J19.1(CON_PIN[0]) U23.9(RX-/TX-)
TX-: J19.2(CON_PIN[1]) U23.11(RX+/TX+)
TX_N0: R214.1 U22.4(TRXN0)
TX_P0: R213.1 U22.3(TRXP0)
XTO: TP53.1 U17.10(XTO)
N16771643: C105.2 R91.1 R92.2
N16771875: C106.1 R92.1 R93.1 R94.1
N16774062: C113.1 R106.1 U11.6(VDD)
N16774094: R105.1 U11.4(-IN)
N16774098: C112.1 R105.2
N16774118: C111.1 R104.2
N16774180: R102.1 R103.2 U11.1(/SD)
N16774192: R104.1 U11.3(+IN)
N16775243: R99.2 U10.3(STBY)
N16859821: R170.2 U17.19(SI/EXTEEP)
N16859918: R172.1 U17.3(I2CSEL)
N16859920: C136.1 R173.2 U17.22(PDN)
N16861141: R144.1 U13.3(CLK)
N16861143: R145.1 U13.4(DATA)
N16861165: R147.1 U14.3(CLK)
N16861167: R148.1 U14.4(DATA)
N16861179: C123.1 C124.1 FB14.1 R130.1 U14.1(VDD)
N16861294: R154.1 U15.3(CLK)
N16861296: R155.1 U15.4(DATA)
N16861324: C125.1 C126.1 FB15.1 R131.1 U15.1(VDD)
N16861434: R157.1 U16.3(CLK)
N16861436: R158.1 U16.4(DATA)
N16861448: C127.1 C128.1 FB16.1 R132.1 U16.1(VDD)
N16861556: C121.1 C122.1 FB13.1 R129.1 U13.1(VDD)
N16862955: C146.1 C147.1 R180.1 R184.1
N16863107: C150.1 R183.1 U18.5(Vout)
N16863121: C152.1 R185.1 U18.3(STBY)
N16863211: C158.1 R191.1 U20.3(STBY)
N16871764: C148.1 C149.1 R181.1 R182.1
N16876325: D14.2(CATHODE) J15.2 U19.5(VO+)
N16876337: D15.2(CATHODE) J15.1 U19.8(VO-)
N16876351: C155.1 R189.1 U19.6(VDD)
N16876358: R190.1 U19.4(-IN)
N16876368: C154.2 R190.2
N16876378: C153.2 R188.2
N16876406: R186.1 R187.2 U19.1(/SD)
N16876412: R188.1 U19.3(+IN)
N16900408: C164.2 Q2.1(GATE) R198.2 R237.2 R239.2
N16904771: C175.2 R209.1 R210.2 Y3.3
N16904783: C176.2 R210.1 R211.1 Y3.1
N17238740: C105.1 R89.1 R90.2
N17639490: R267.2 U24.1(ISET)
N17639502: C194.2 U24.12(C2-)
N17639539: C195.1 U24.10(C1+)
N17639549: C194.1 U24.9(C2+)
N17639559: C195.2 U24.11(C1-)
N17639566: C196.1 R260.1 U24.13(VIN)
N17705583: C187.1 R234.2 R298.2 U22.21(RESET_N)
N17705597: R218.2 U22.26(CRS/CRS_DV)
N17705611: R220.2 U22.9(RXD[0])
N17705613: R221.2 U22.10(RXD[1])
N17705750: R235.1 U22.30(NC)
N17705784: R226.2 U22.32(XTAL_OUT)
N17705826: R212.2 U22.15(TXC)
N17705884: C184.1 C185.1 U22.2(AVDDL_REG)
N17705928: C182.1 C183.1 U22.29(DVDDL_REG)
N17706002: R225.2 U22.28(RXER)
N17706200: R217.1 U22.1(PBIAS)
N17706222: C179.2 U23.7(CT2)
N17706227: D16.1 R228.2 U23.10(CT3) U23.13(MCT) U23.15(CT4)
N17706250: C178.2 U23.5(CT)
N17706256: C177.2 U23.2(CT1)
N17706349: J19.11(CON_PIN[10]) R224.1
N17706354: J19.13(CON_PIN[12]) R231.1
N17706406: C186.2 R228.1
N17919056: C107.1 R95.2 R96.1
N17919062: C212.2 R101.2 R312.1
N17919066: C108.1 R96.2 R97.1 R98.2
N17919088: C193.2 R100.1 R312.2 R313.1
N18199643: R265.1 U24.4(D3)

Not connected (* = marked no-connect by the designer): J11 4* 5* 23* 24* 30*; J12 11* 12* 14* 15* 17*; J17 10* 11* 12* 13* 14* 15* 17* 18* 20* 21* 22* 25* 26* 27* 28* 29* 30* 31* 37* 38* 40*; J19 4(CON_PIN[3])* 5(CON_PIN[4])* 7(CON_PIN[6])* 8(CON_PIN[7])* 15(NC1)* 16(NC2)*; J22 2(XR)* 3(YD)* 4(XL)* 5(YU)* 18(VSYNC)* 19(HSYNC)* 20(ENABLE)* 21(DOTCLK)* 22(SDA)* 41(SDO)*; U10 4(NC)*; U11 2(NC)*; U18 4(NC)*; U19 2(NC)*; U20 4(NC)*; U22 11(RXD[2]/INT_N)* 13(RXC)* 18(TXD[2])* 19(TXD[3])* 27(COL)*; U23 4(NC1)* 12(NC2)*; U24 2(NC2)* 3(NC1)*

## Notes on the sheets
sheet 8
- AUDIO
- MICL
- NC
- -
- +
- NC
- NC
- NC
- Reserved
- NC
- NC
- NC
- Reserved for debug
- Reserved for debug
- SPK
- NC
- NC
- Reserved
- Note：The 0Ω resistance in         is used for measuring power consumption
  and can be removed in the product board.
sheet 9
- DVP
- MIPI_DVP_CAMERA
- NC
- NC
- NC
- NC
- NC
- NC
- NC
- Note：The 0Ω resistance in         is used for measuring power consumption
  and can be removed in the product board.
- MIPI 2Lane CAMERA 1
sheet 10
- EMMC_DMIC
- EMMC
- NC
- DIMC
- NC
- NC
- NC
- NC
sheet 11
- I2S_CODEC
- Note：The 0Ω resistance in         is used for measuring power consumption
  and can be removed in the product board.
- NC
- NC
- I2C_SID
- 7 bit address
- 1
- 0x19
- 0
- 0x18(default)
- MIC2
- MIC1
- -
- NC
- NC
- -
- NC
- NC
- +
- +
- Codec POWER
- NC
- NC
- NC
- NC
- Reserved
- Reserved
- SPK
- NC
- NC
- Reserved
sheet 12
- SD_WIFI_AF_MOTOR
- WIFI CONNECTOR
- SD CARD
- NC
- SPI AF MOTOR
- Match with YT30018DB
- NC
- Note：The 0Ω resistance in         is used for measuring power
  consumption and can be removed in the product board.
sheet 13
- ETH_PHY
- NC
- LED MODE
- NC
- RMII MODE
- NC
- NC
- NC
- REF_CLK Output RMII2
- NC
- PHY Address : 00000b
- NC
- NC
- Note: R235 Compatible with JL1101
- NC
- NC
- NC
- NC
- NC
- NC
- NC
sheet 14
- SLCD_BT656_OUT
- Note：The 0Ω resistance in         is used for measuring power consumption
  and can be removed in the product board.
- 2.8' SLCD WZ028QVFBA006-RT
- NC
- NC
- SLCD_BackLight_Power
- NC
- NC
- NC
- NC
- NC
- NC
- NC
- NC
- BKL_EN
  0 : BACK LIGHT SHUTDOWN
  1 : BACK LIGHT ENABLE
  PWM : DIMMING
- I(mA)=255*600mV/6.19K=24.7mA/CH
- BT656
